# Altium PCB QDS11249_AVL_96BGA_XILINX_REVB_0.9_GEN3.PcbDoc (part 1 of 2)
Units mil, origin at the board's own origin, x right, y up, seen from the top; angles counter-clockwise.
Board outline 3000.03 x 2525.24 mil, 10 copper layers (Top Layer, GND1 - COMMON, INT1, PWR1 - VCC, GND2 - VSS, PWR2 - VCC/VCCIO-EXIT, GND3 - VSSIO, PWR3 - VCCIO, GND4 - COMMON, Bottom Layer), stack 67.702 mil thick; 142 components, 64 nets, 703 pads, 440 vias.
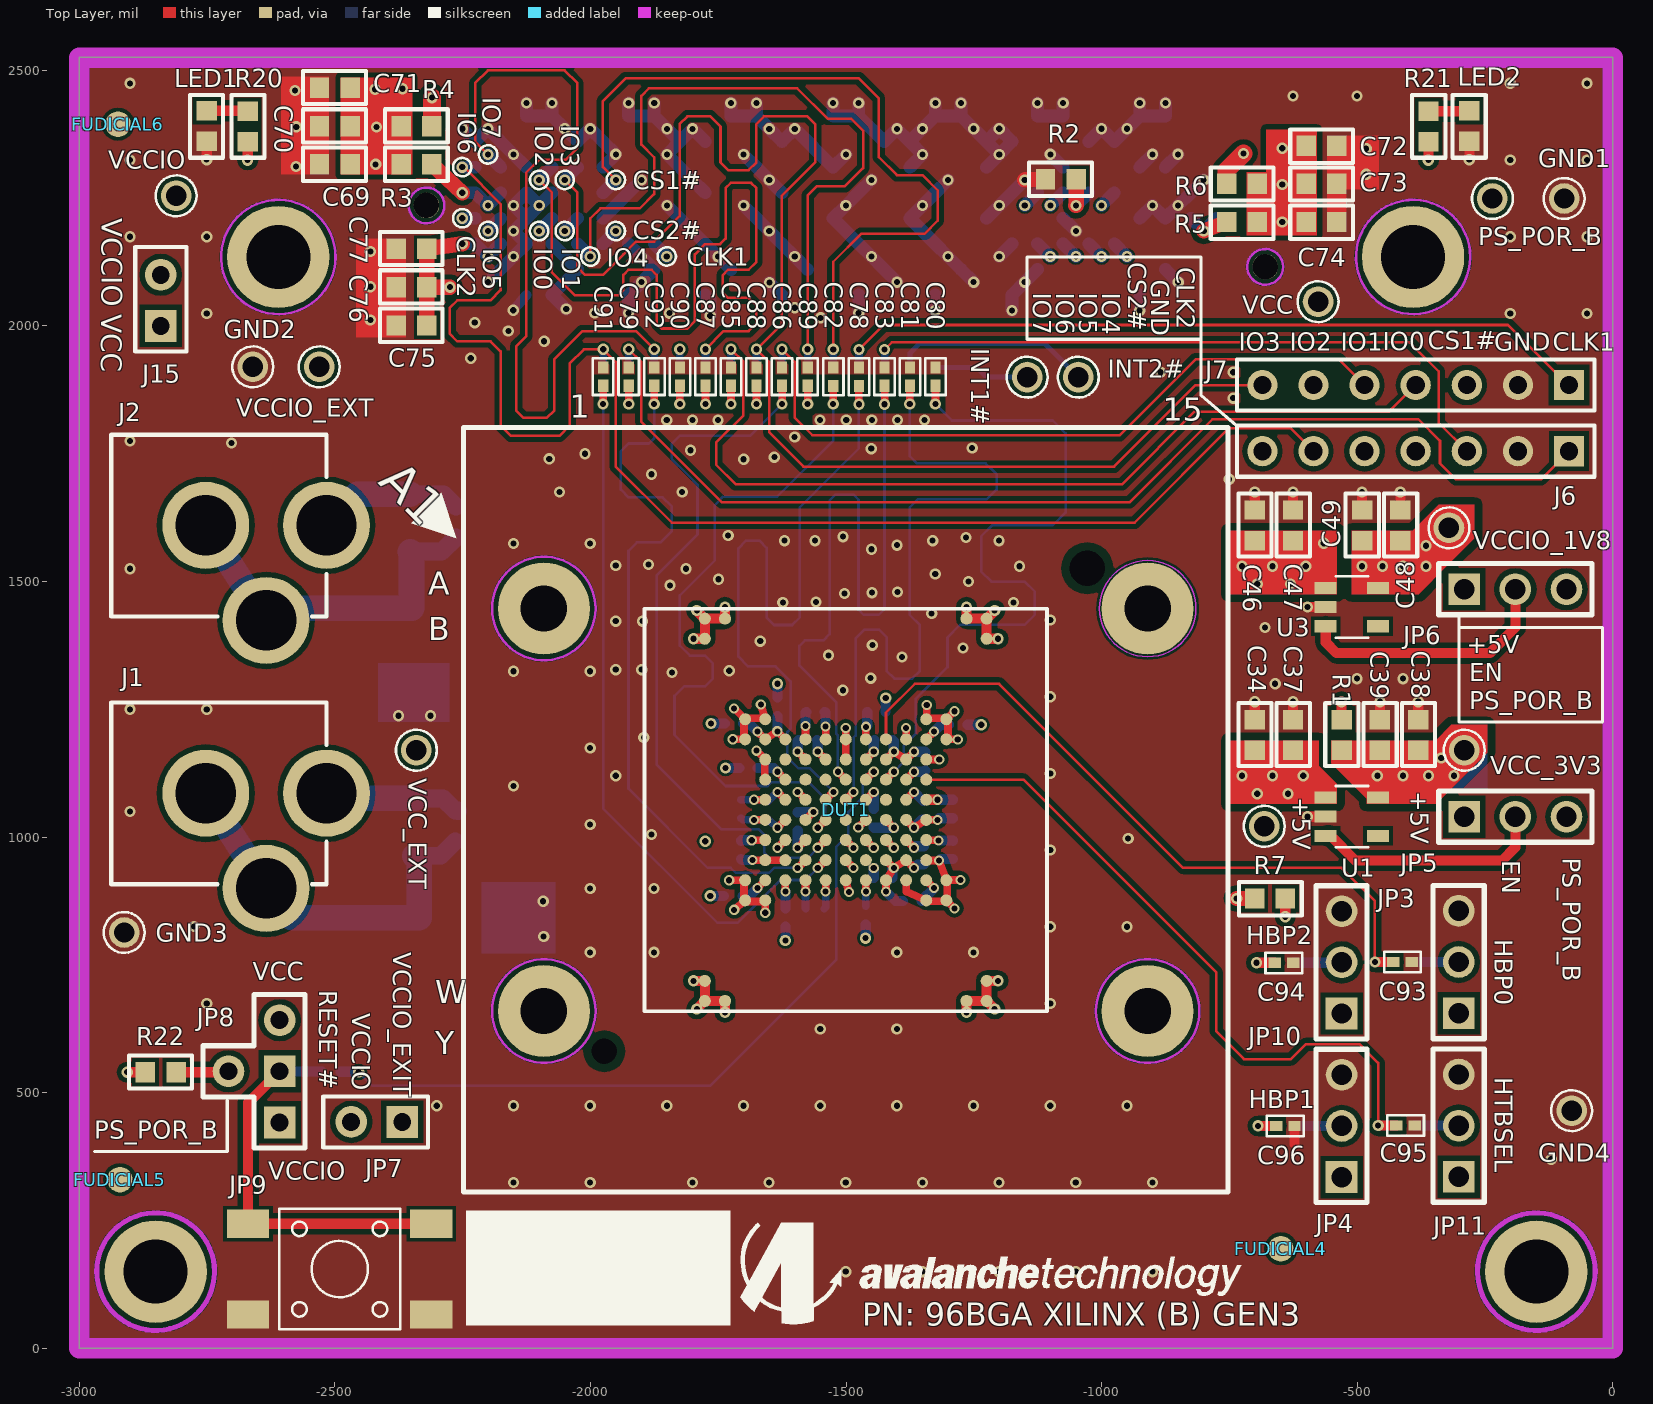
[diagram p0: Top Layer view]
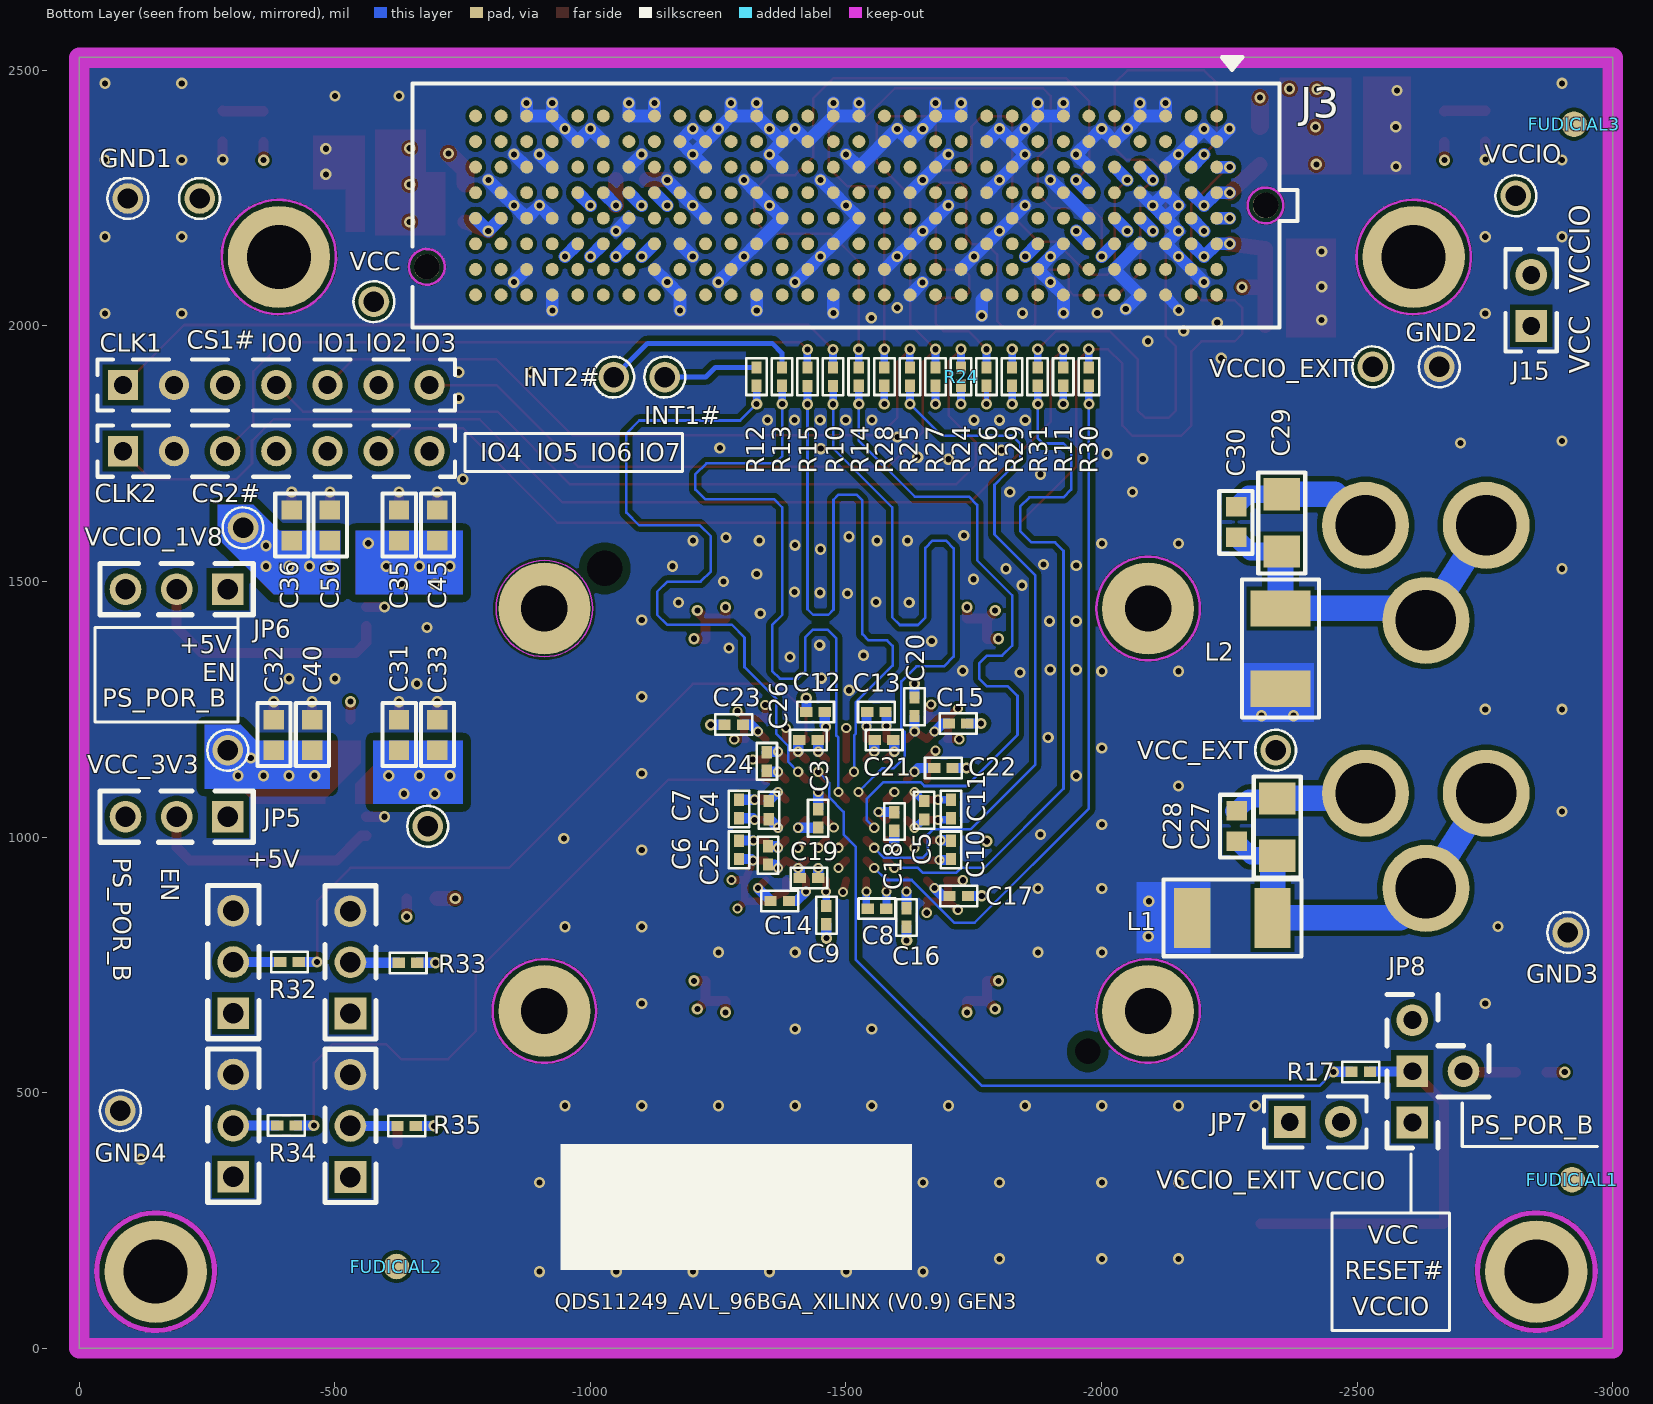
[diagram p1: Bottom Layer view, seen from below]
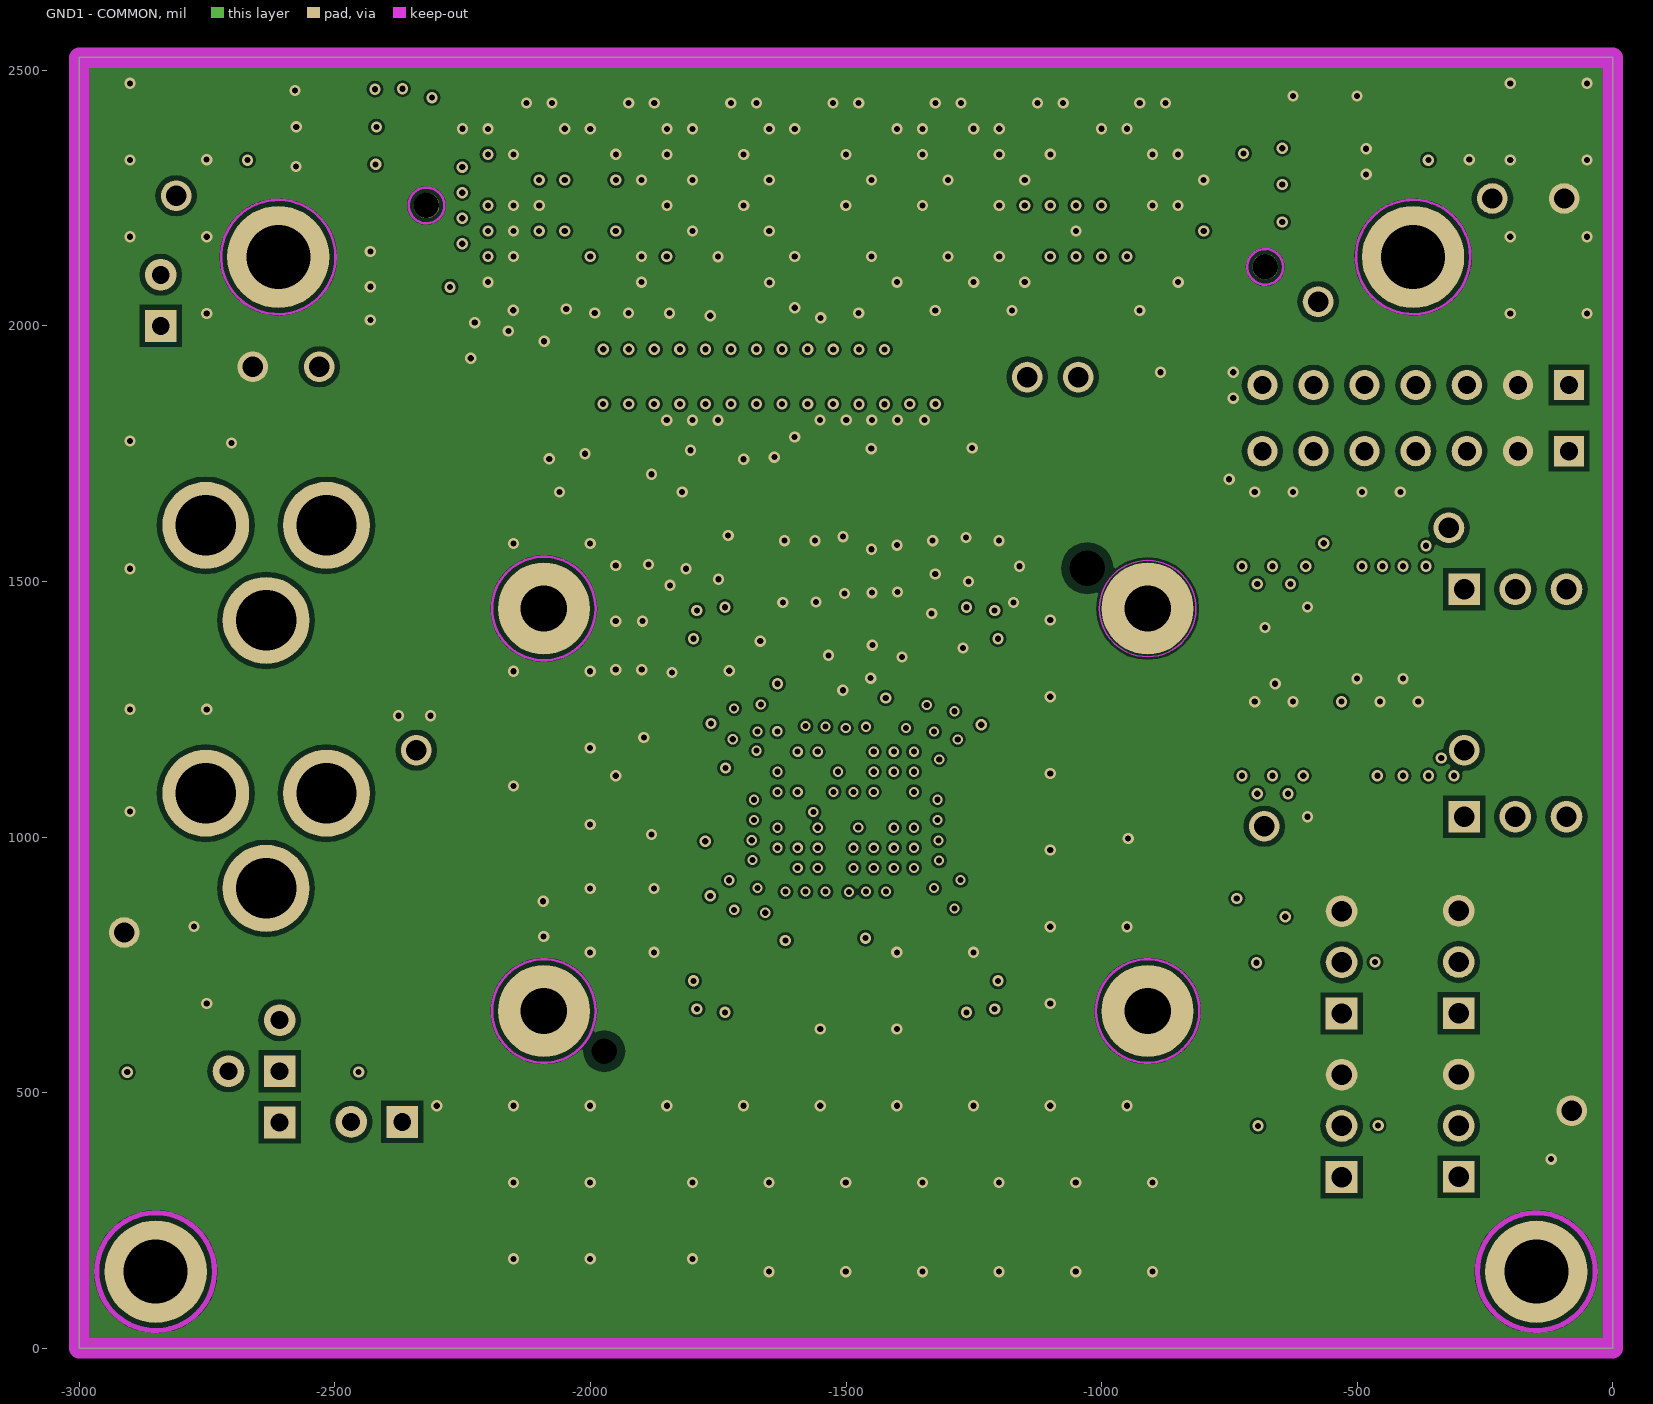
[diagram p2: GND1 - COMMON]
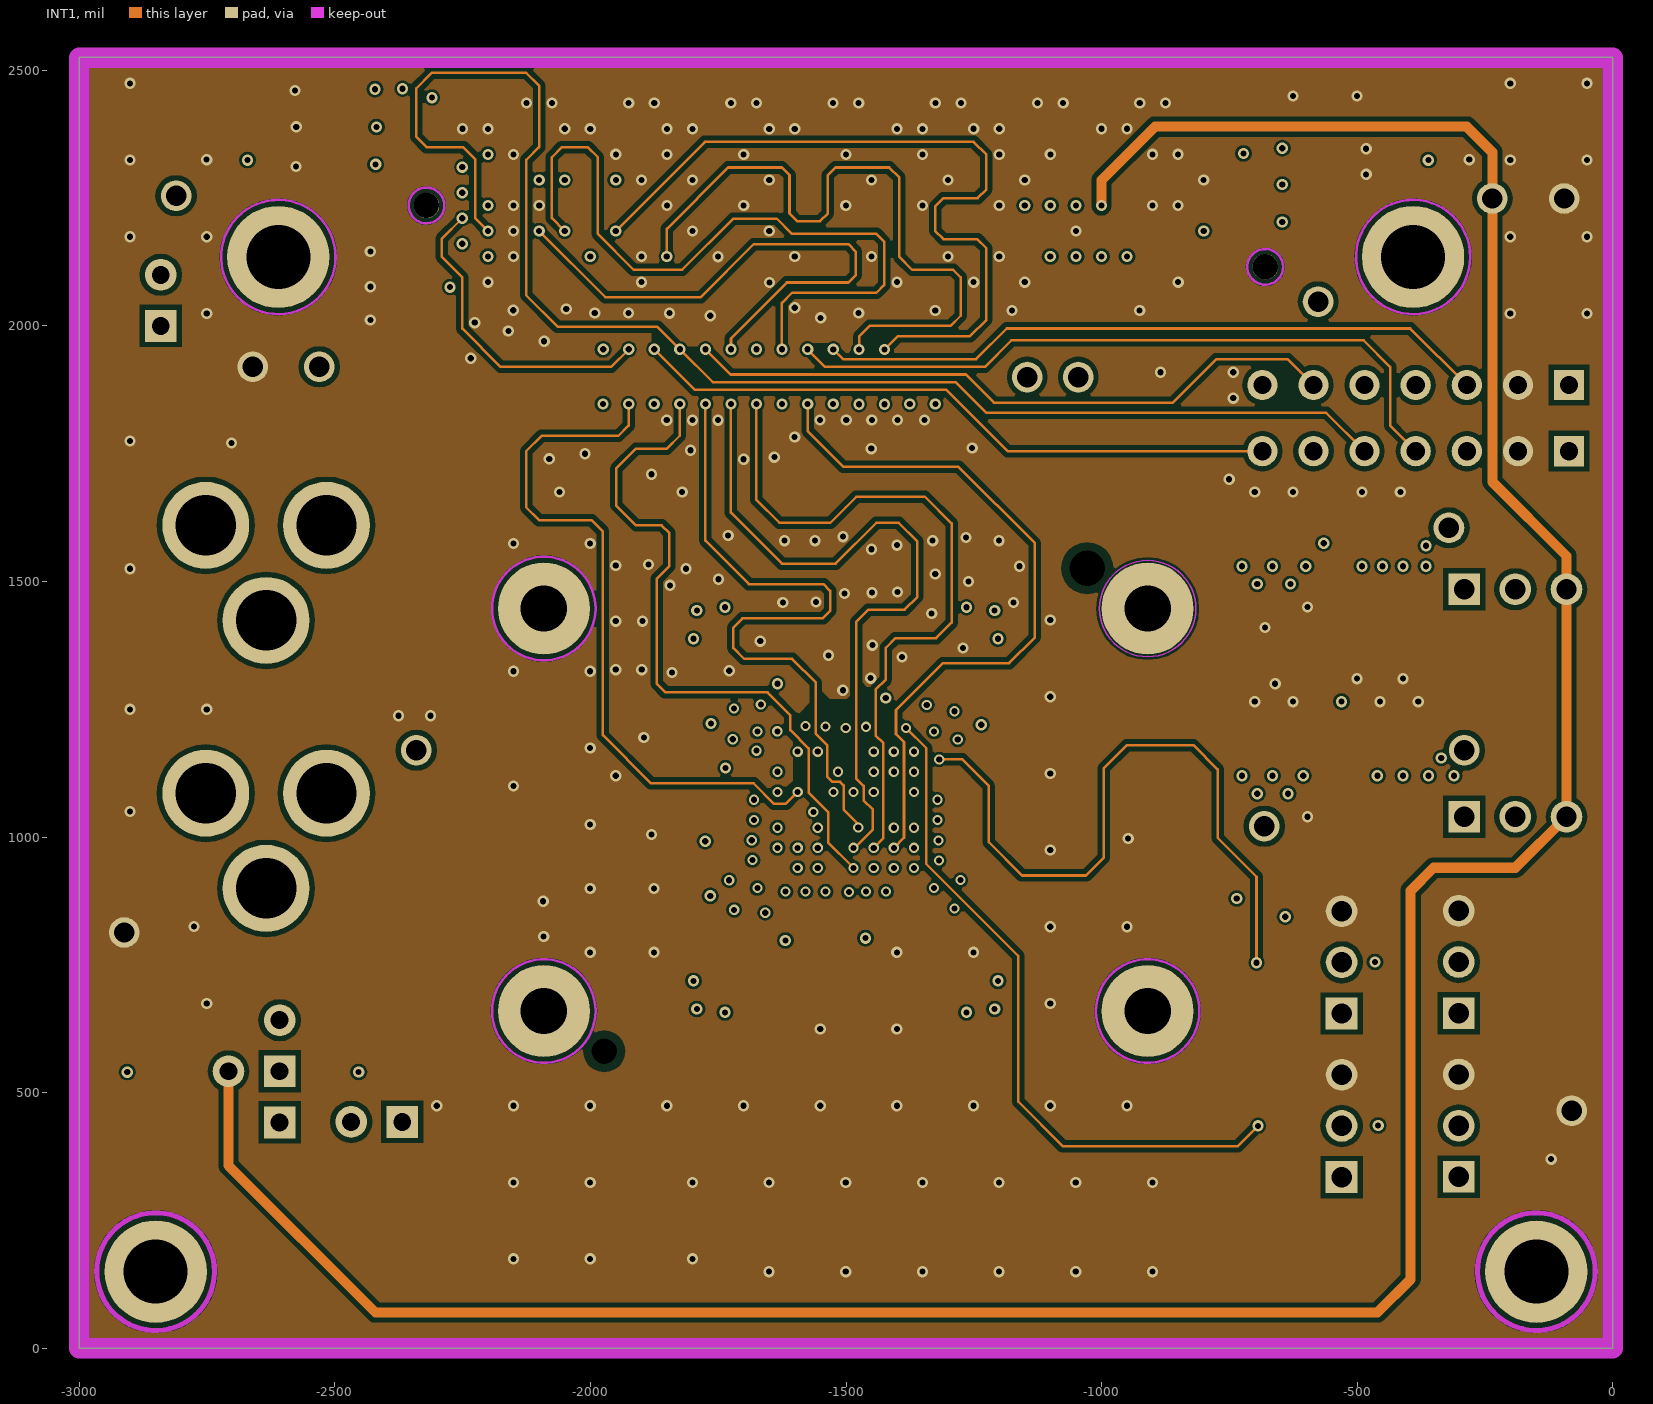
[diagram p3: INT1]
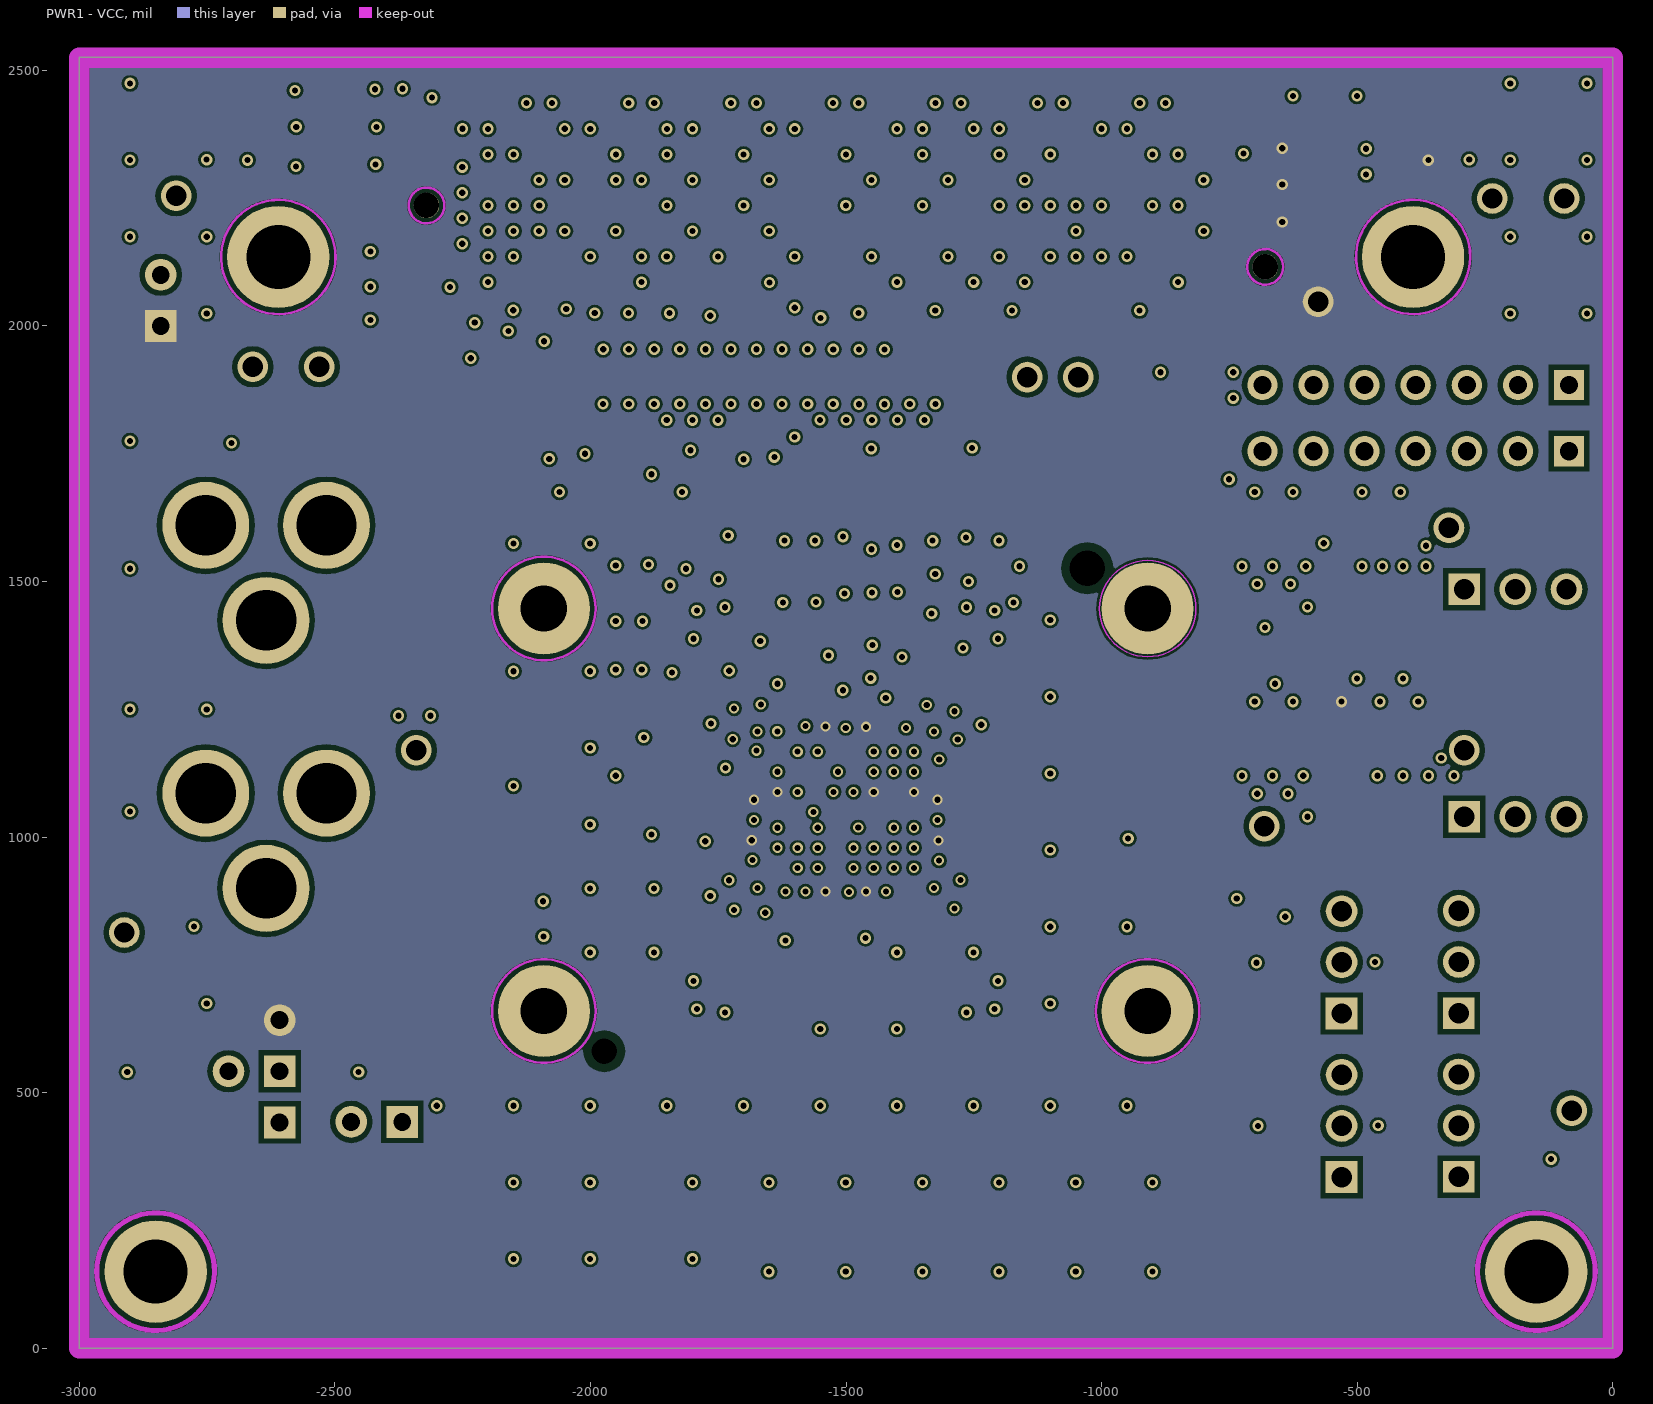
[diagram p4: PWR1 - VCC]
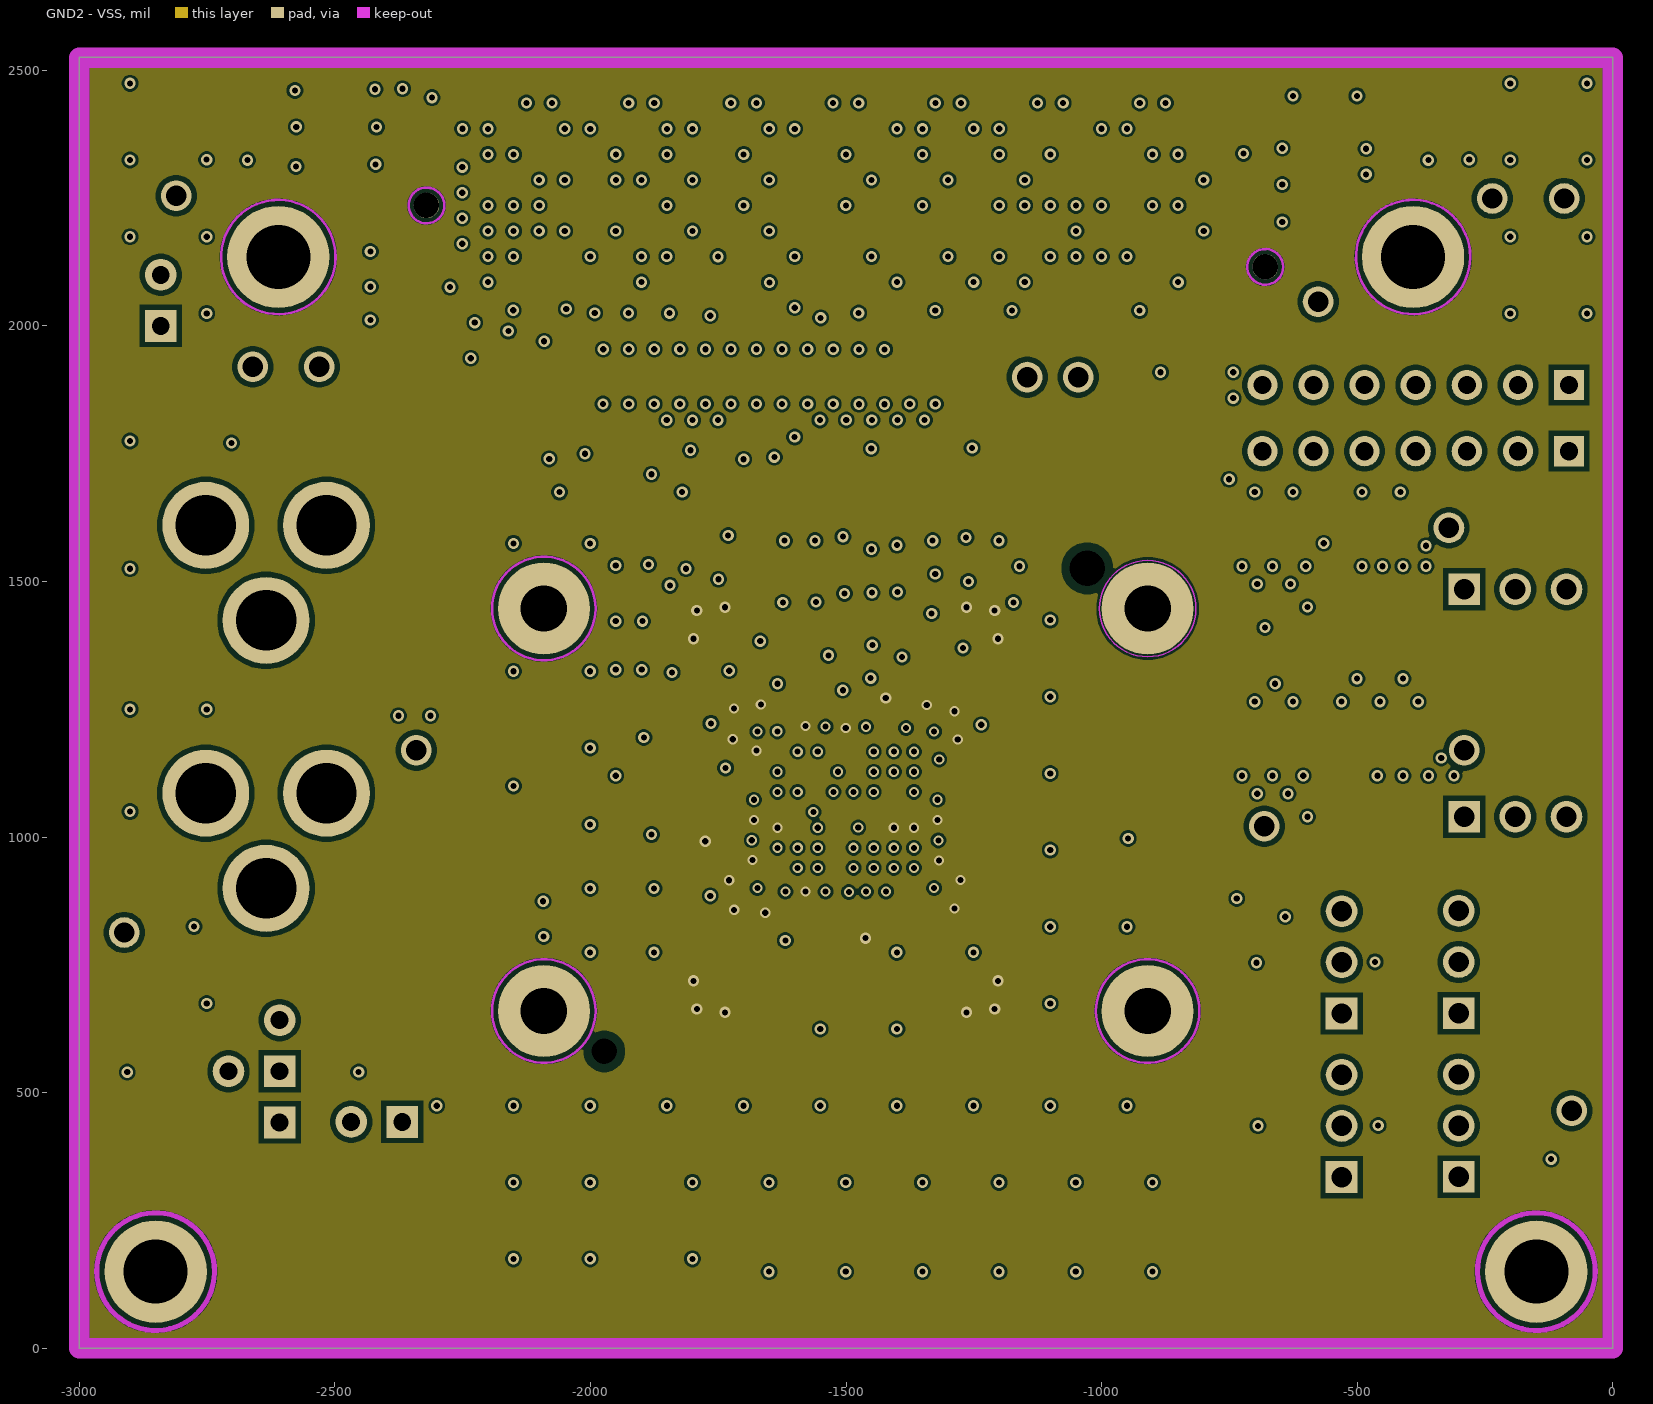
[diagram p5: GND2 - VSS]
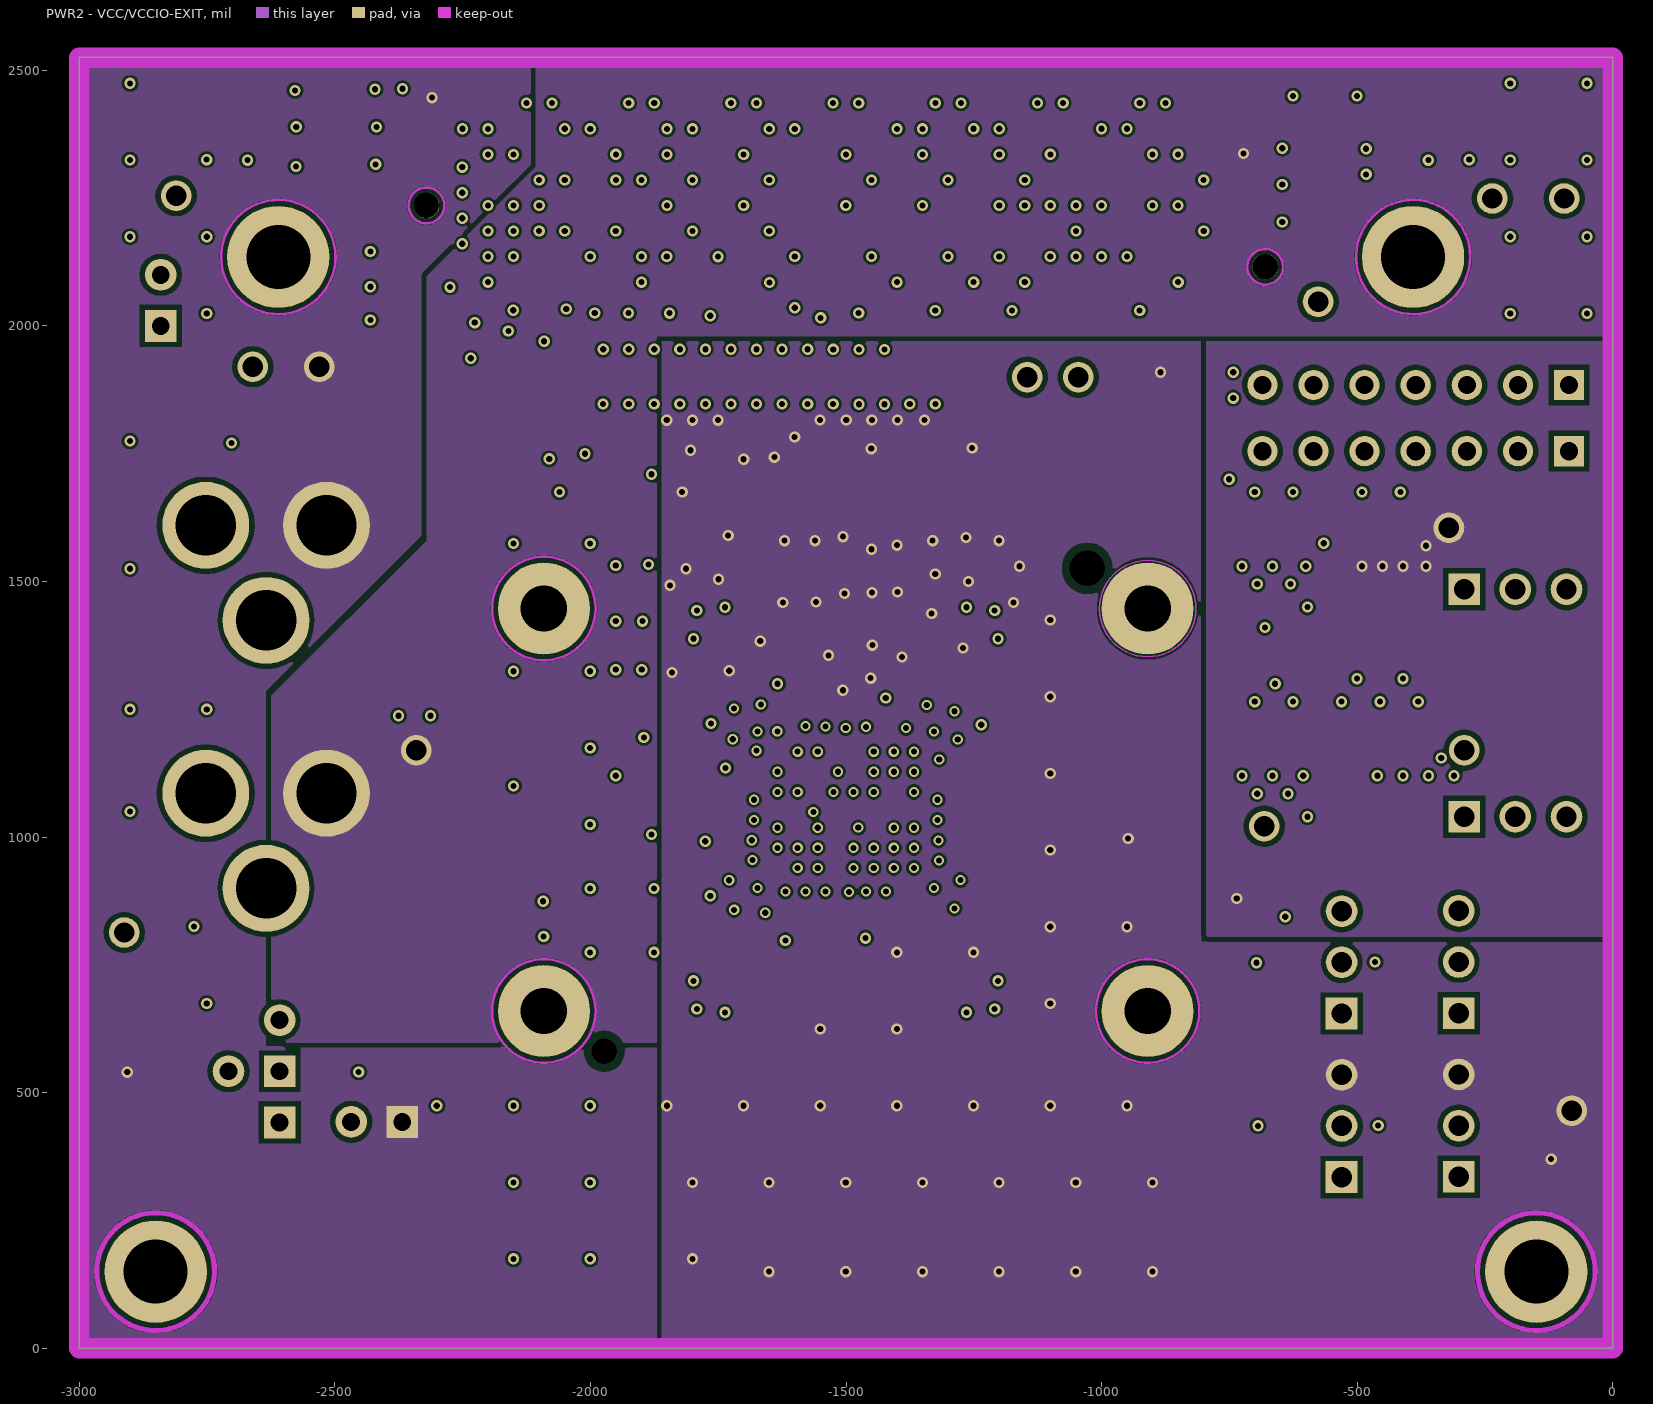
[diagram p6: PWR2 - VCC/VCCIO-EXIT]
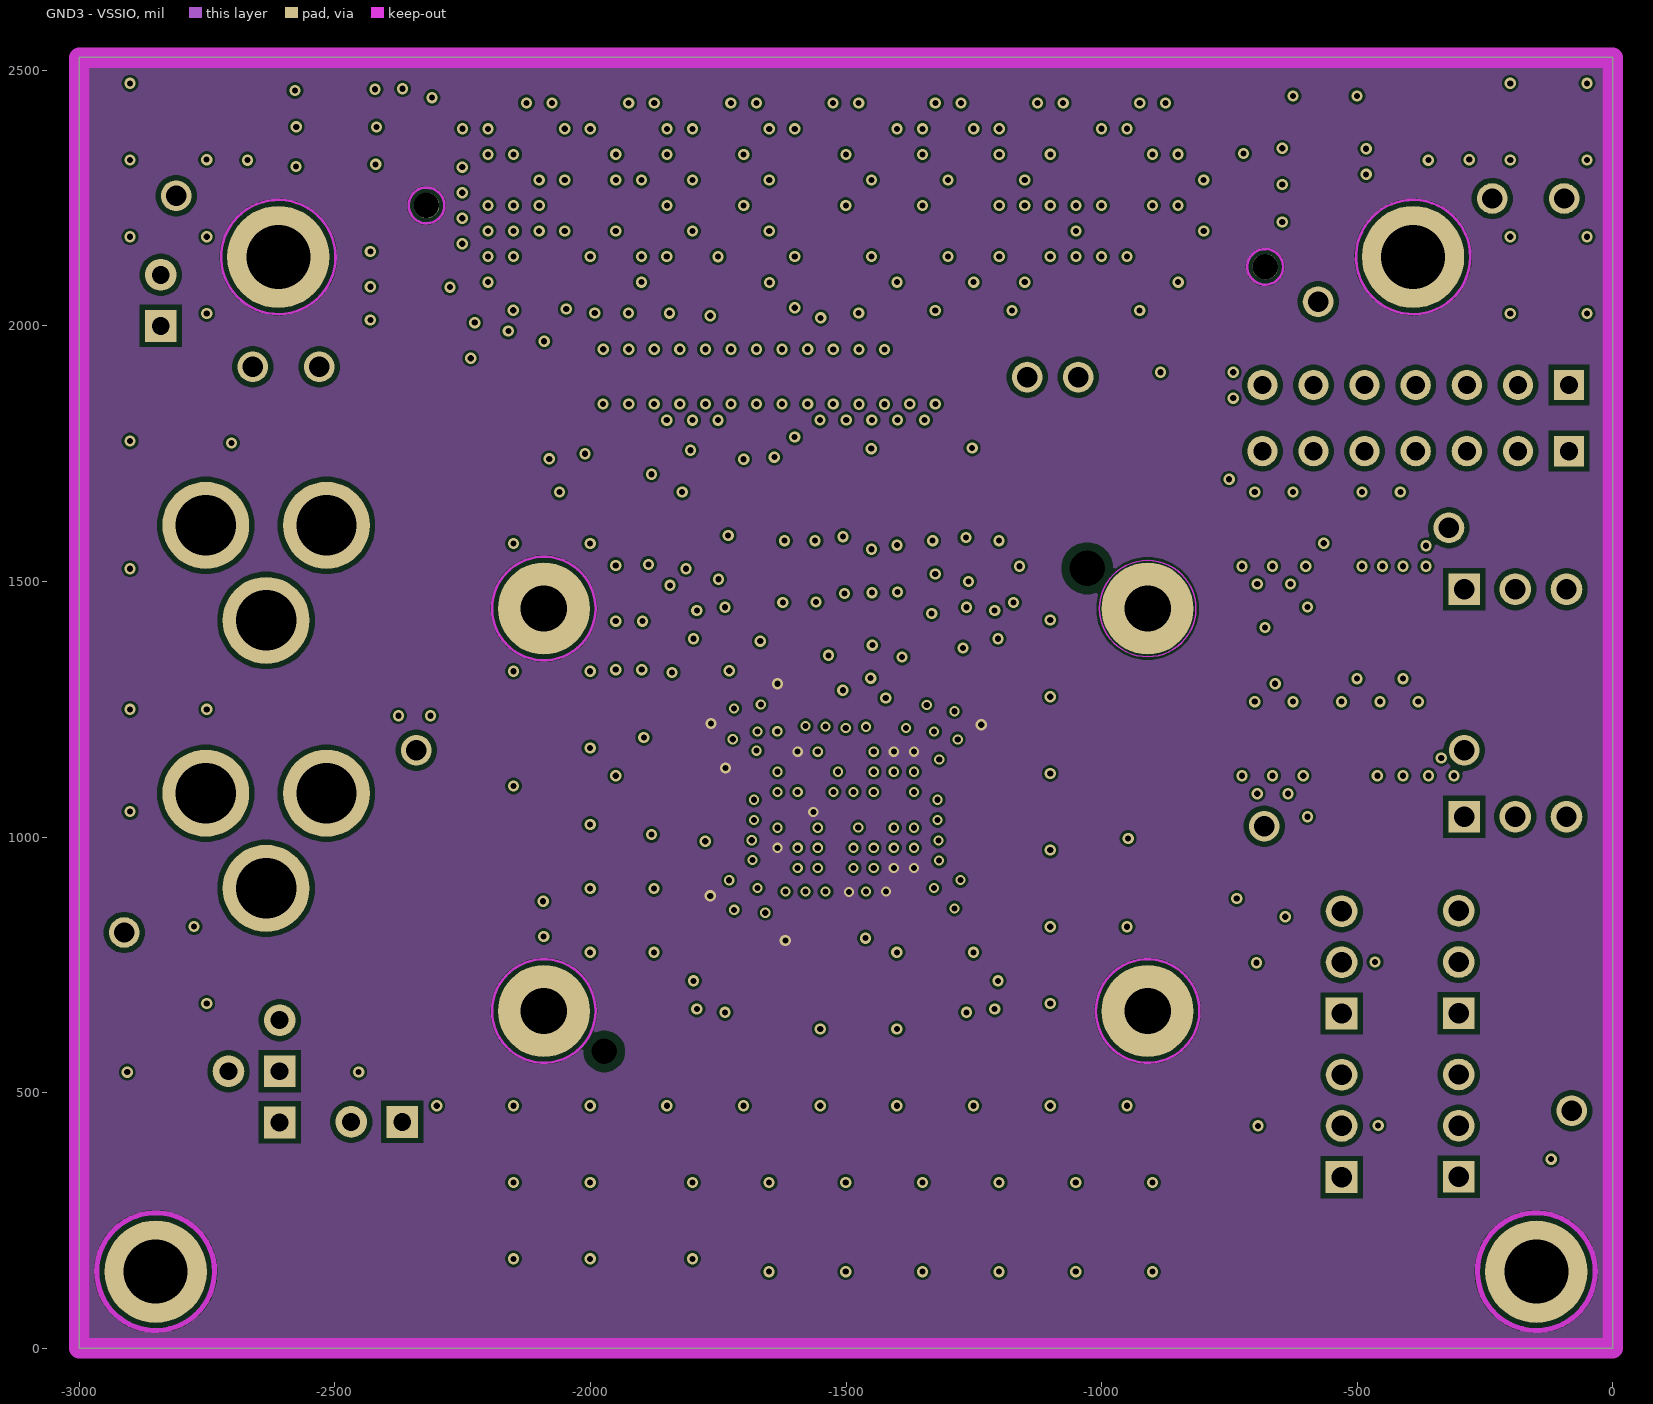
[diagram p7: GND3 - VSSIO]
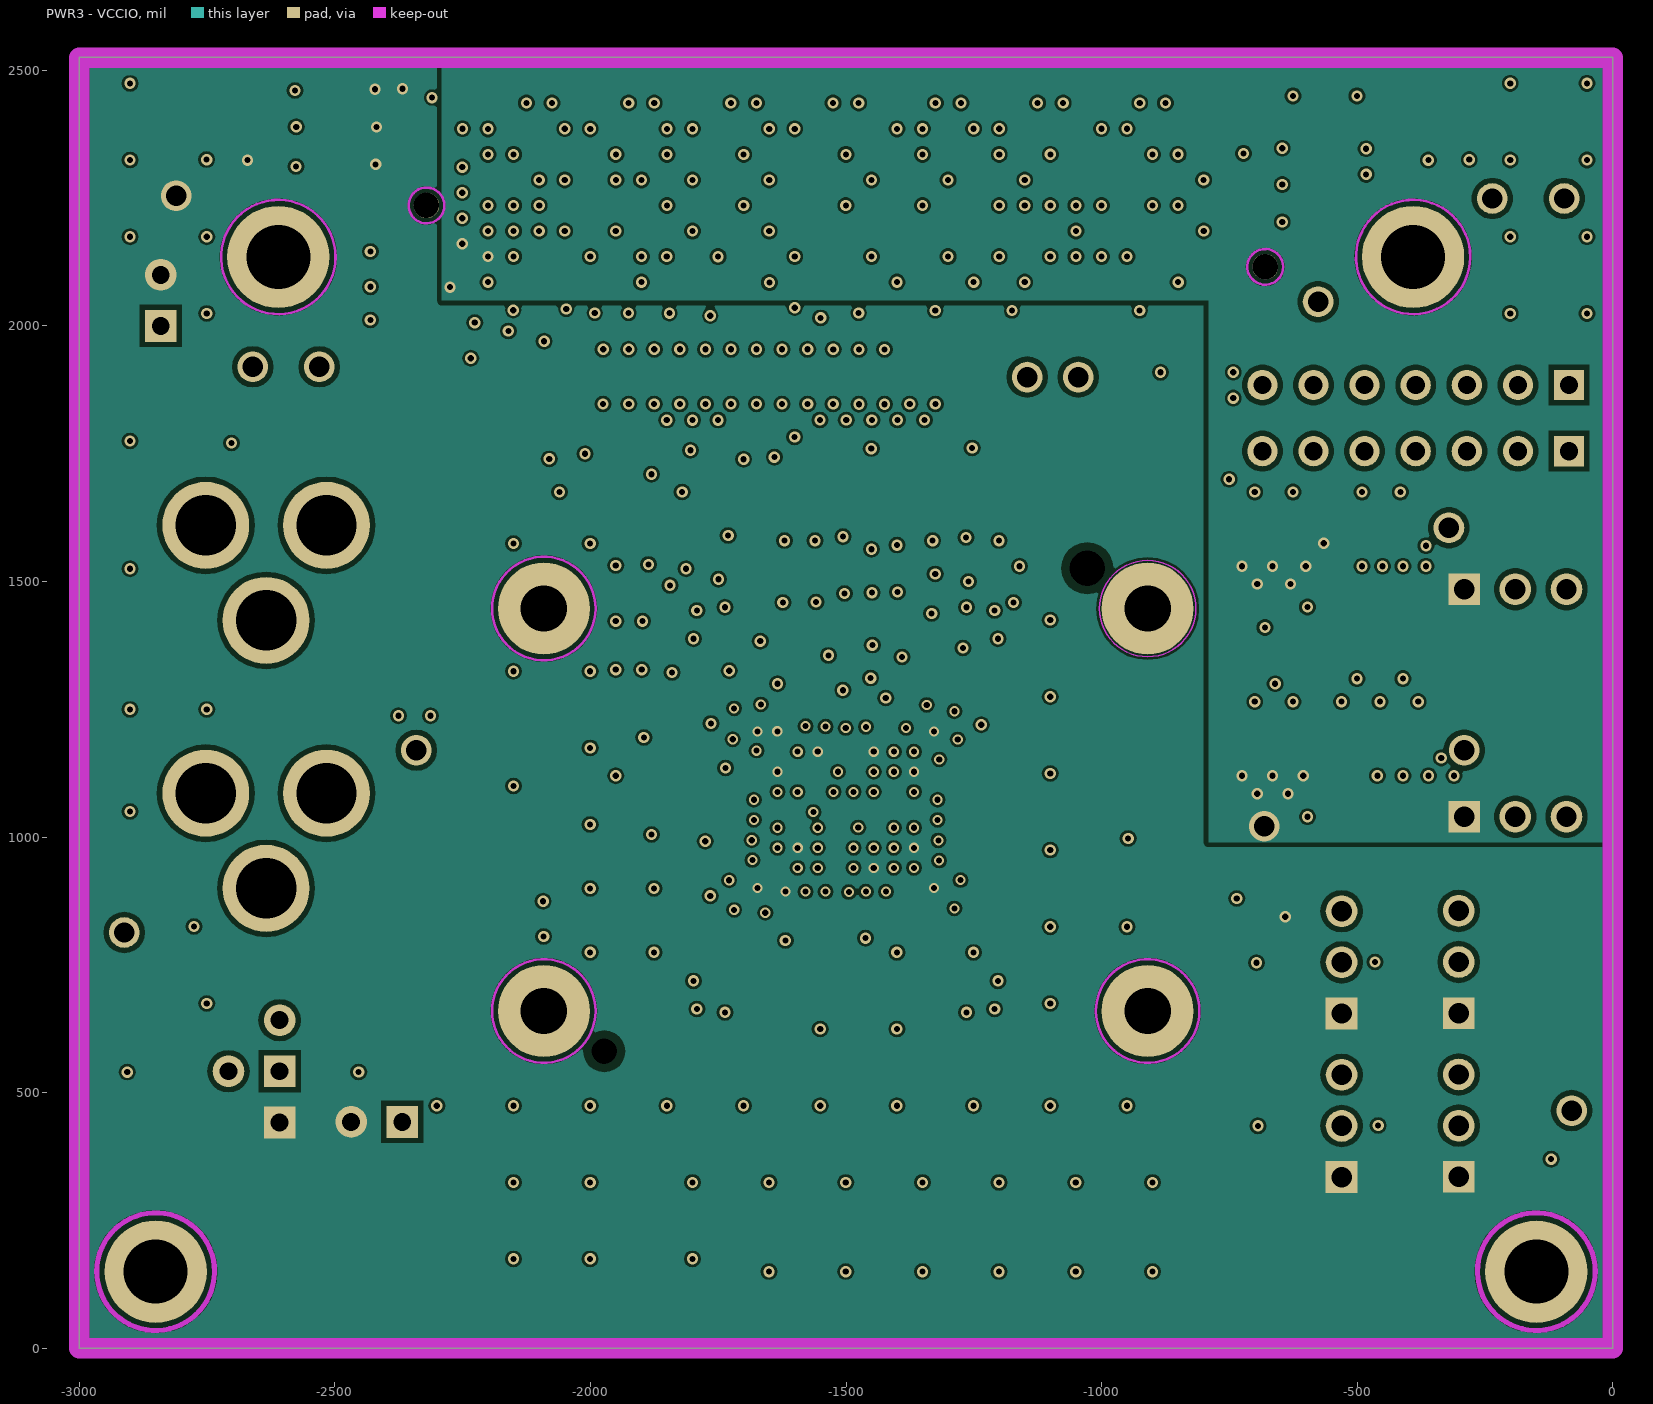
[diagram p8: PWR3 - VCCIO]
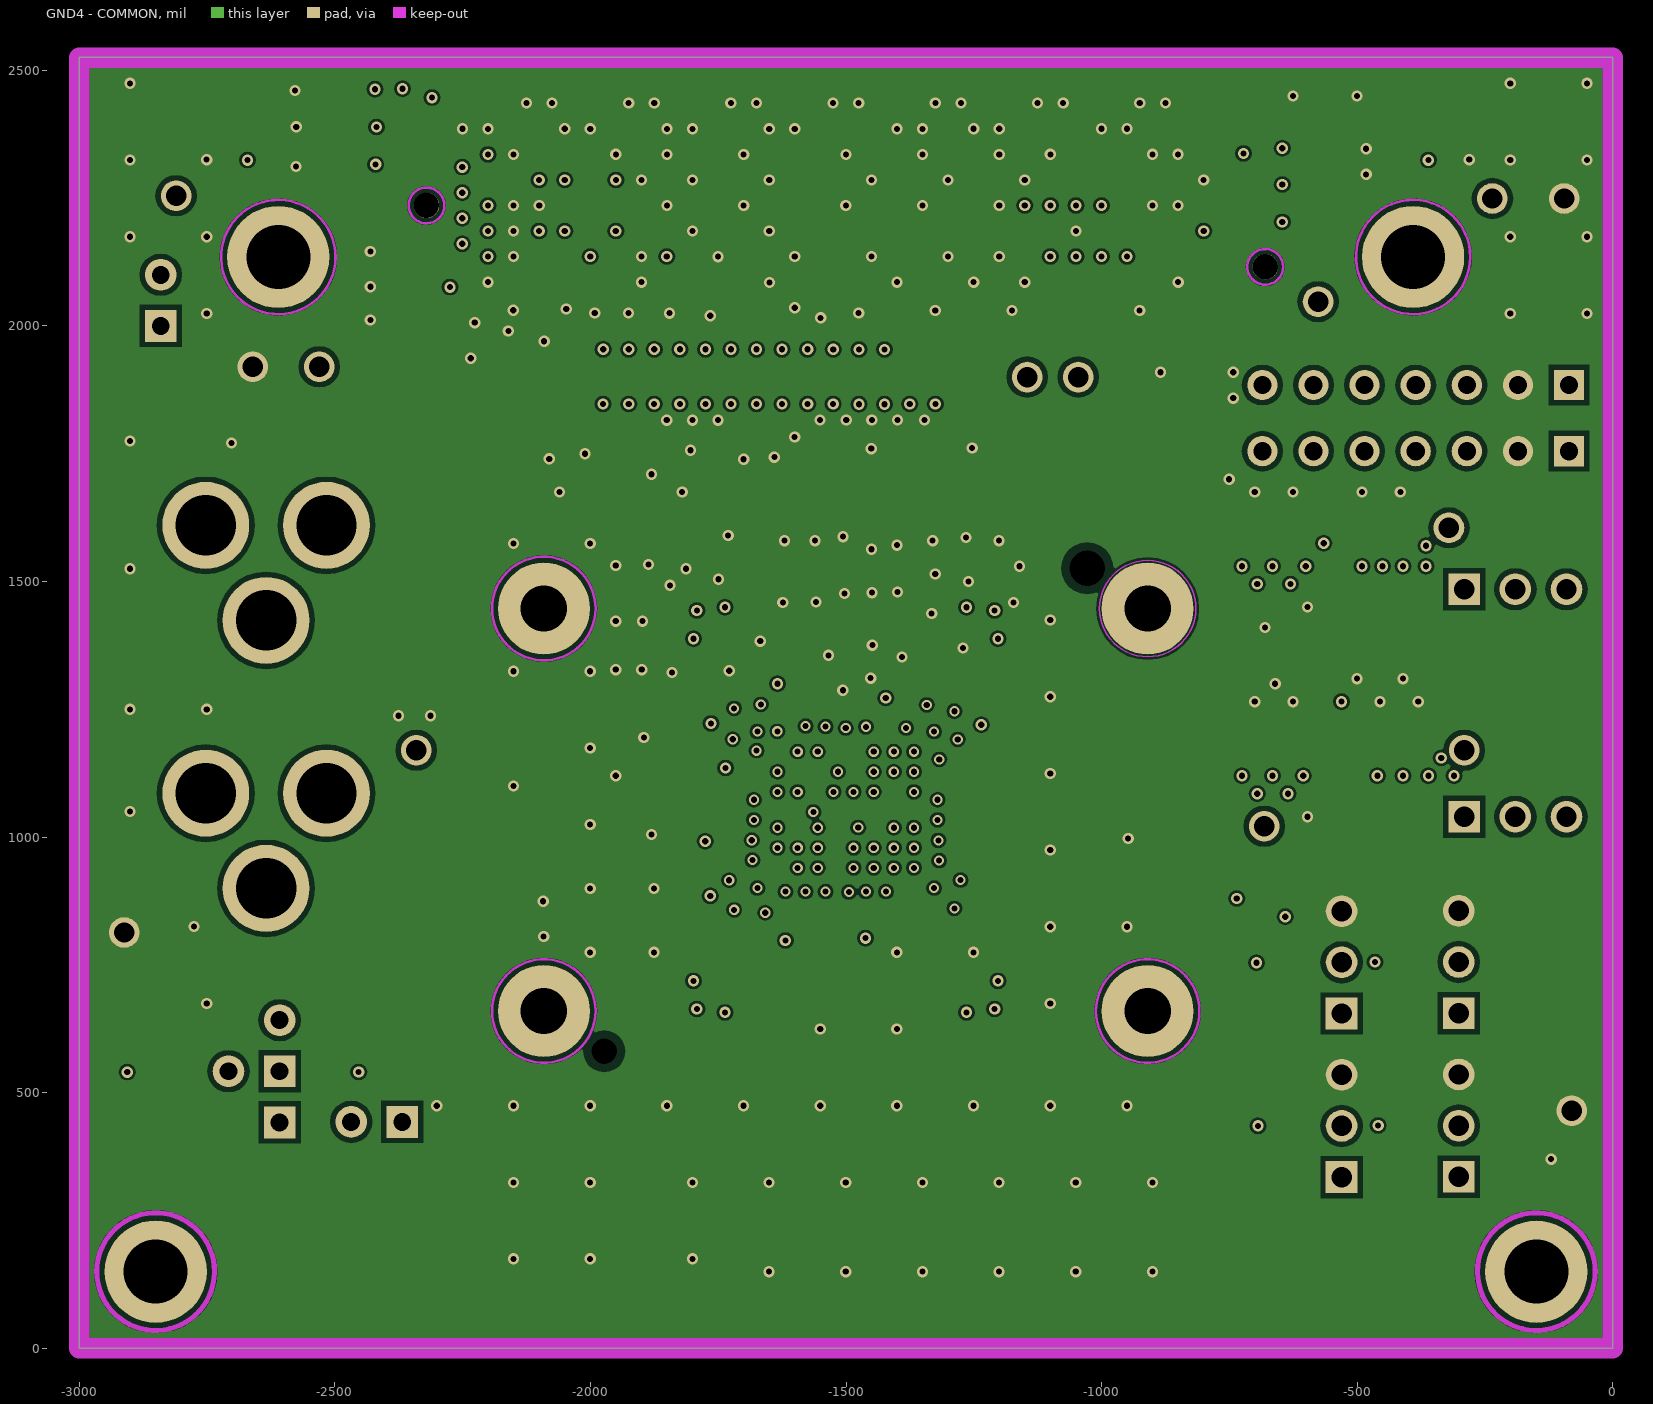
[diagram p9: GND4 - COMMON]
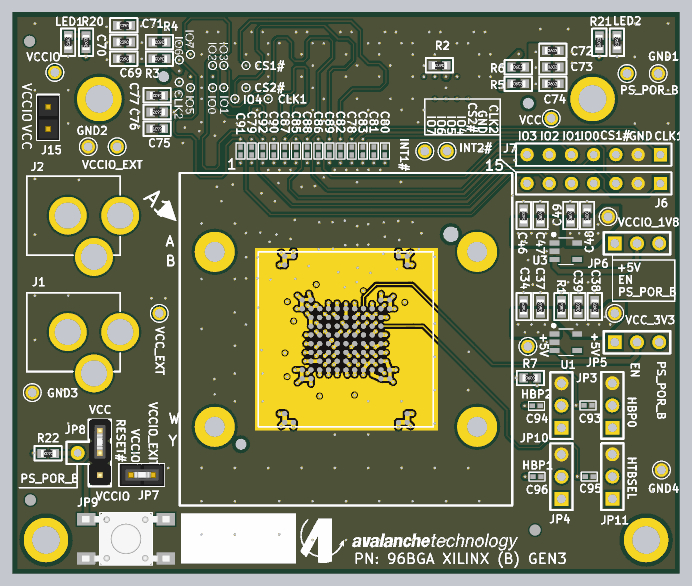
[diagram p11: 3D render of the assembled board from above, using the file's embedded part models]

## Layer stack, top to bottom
Top Solder: solder mask 1, Solder Resist, Dk 3.5
Top Layer: signal copper 6
Dielectric1: core 15, Dk 4.2
GND1 - COMMON: signal copper 1.378
Dielectric 1: prepreg 2.8, Dk 4.1
INT1: signal copper 1.417
Dielectric 2: prepreg 2.8, Dk 4.1
PWR1 - VCC: signal copper 1.417
Dielectric 3: prepreg 2.8, PP-006, Dk 4.1
GND2 - VSS: signal copper 1.378
Dielectric 4: prepreg 2.8, Dk 4.1
PWR2 - VCC/VCCIO-EXIT: signal copper 1.378
Dielectric 8: prepreg 2.8, PP-006, Dk 4.1
GND3 - VSSIO: signal copper 1.378
Dielectric 7: prepreg 2.8, Dk 4.1
PWR3 - VCCIO: signal copper 1.378
Dielectric 5: prepreg 2.8, Dk 4.1
GND4 - COMMON: signal copper 1.378
Dielectric 6: core 10, Dk 4.2
Bottom Layer: signal copper 6
Bottom Solder: solder mask 1, Solder Resist, Dk 3.5

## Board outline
-3000.02,-0.01 -0.02,-0.01 ccw(c-0.02,0) 0,0 0,214.17 0,1725.17 0,2525.22 cw(c-0.02,2525.22) 0,2525.22 ccw(c-0.02,2525.22) -0.02,2525.23 -3000.02,2525.23 ccw(c-3000.02,2525.22) -3000.03,2525.22 -3000.03,1725.22 -3000.03,16.13 -3000.03,0 ccw(c-3000.02,0)

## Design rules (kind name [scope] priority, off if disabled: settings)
Clearance Keepout [All vs OnLayer('Keep-Out Layer')] p1: gap=0 ignorepadtopadclearanceinfootprint=FALSE
Clearance [All] p2: gap=7 ignorepadtopadclearanceinfootprint=FALSE except(5: Arc-Hole Track-SMDPad Track-THPad Track-Via Track-Fill SMDPad-Via THPad-Fill Via-Poly; 10: Arc-Poly Arc-Region Track-Poly SMDPad-SMDPad SMDPad-THPad SMDPad-Region THPad-Poly THPad-Region Via-Region Fill-Poly Poly-Poly; 15: Fill-Region Poly-Region)
ComponentClearance [All] p1 off: gap=10 collisioncheckmode=3 verticalgap=10 showdistances=FALSE
FabricationTestPointUsage TestPointUsage [All] p1: valid=0 allowmultiple=FALSE
FabricationTestpoint Testpoint [(IsPad And (OnTopLayer Or OnBottomLayer))] p1: side=3 testpointundercomponent=TRUE minsize=40 maxsize=100 preferedsize=60 minholesize=0 maxholesize=40 preferedholesize=32 testpointgrid=1 allowsidetop=TRUE allowsidebottom=TRUE usegrid=TRUE gridtolerance=0.01
Height [All] p1 off: minheight=0 maxheight=1000 prefheight=500
HoleSize [All] p1 off: absolutevalues=TRUE maxlimit=100 minlimit=1 maxpercent=80.000 minpercent=20.000
MatchedLengths MG03 [InNetClass('MG03 - Socket to Connector')] p1: tolerance=100 checknetsindiffpair=FALSE checkdiffpairvsdiffpair=TRUE checkxsignals=TRUE checkothers=TRUE
MatchedLengths MG02 [InNetClass('MG02 - R to Connector')] p2: tolerance=100 checknetsindiffpair=FALSE checkdiffpairvsdiffpair=TRUE checkxsignals=TRUE checkothers=TRUE
MatchedLengths MG01 [InNetClass('MG01 - Socket to R')] p3: tolerance=100 checknetsindiffpair=FALSE checkdiffpairvsdiffpair=TRUE checkxsignals=TRUE checkothers=TRUE
PlaneClearance [All] p1: clearance=6
PlaneConnect THERMAL [InComponentClass('THERMAL')] p1: planeconnectstyle=Relief reliefexpansion=20 reliefentries=4 reliefconductorwidth=10 reliefairgap=10
PlaneConnect [All] p2: planeconnectstyle=Direct reliefexpansion=25 reliefentries=4 reliefconductorwidth=10 reliefairgap=12
PolygonConnect THERMAL1 [InComponentClass('Thermal') vs InNet('GND')] p1: connectstyle=Relief reliefconductorwidth=20 reliefentries=4 polygonreliefangle="90 Angle" airgapwidth=20
PolygonConnect [All] p2: connectstyle=Direct reliefconductorwidth=15 reliefentries=4 polygonreliefangle="45 Angle" airgapwidth=15
RoutingVias [All] p1: holewidth=20 width=40 viastyle="Through Hole" minholewidth=20 minwidth=40 maxholewidth=20 maxwidth=40
ShortCircuit [WithinRoom('RoomDefinition_1') & OnTopLayer] p1: allowed=TRUE
SolderMaskExpansion [All] p1: expansion=0 istentingtop=FALSE
Width Width_1 [All] p1: maxlimit=50 minlimit=5 preferedwidth=25
22 further rules are at their usual default settings.

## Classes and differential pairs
net class GROUP2: CLK1_1 CLK2_1 CS1#_1 CS2#_1 INT1#_1 INT2#_1 IO0_1 IO1_1 IO2_1 IO3_1 IO4_1 IO5_1 IO6_1 IO7_1
net class GROUP1: CLK1 CLK2 CS1# CS2# IO0 IO1 IO2 IO3 IO4 IO5 IO6 IO7
component class PAGE03_DC_CONN: C69 C70 C71 C72 C73 C74 C75 C76 C77 J3 R1 R2 R3 R4 R5 R6 R7
component class PAGE02_REGULATOR: +5V C27 C28 C29 C30 C31 C32 C33 C34 C35 C36 C37 C38 C39 C40 C45 C46 C47 C48 C49 C50 C78 C79 C80 C81 C82 C83 C85 C86 C87 C88 C89 C90 C91 C92 C93 C94 C95 C96 CLk2 GND1 GND2 GND3 GND4 INT1# INT2# J1 J2 J6 J7 J15 JP3 JP4 JP5 JP6 JP7 JP8 JP9 JP10 JP11 L1 L2 LED1 LED2 PS_POR_B R10 R11 R12 R13 R14 R15 R17 R20 R21 R22 R24 R25 R26 R27 R28 R29 R30 R31 R32 R33 R34 R35 U1 U3 VCC VCC_3V3 VCC_EXT VCCIO VCCIO_1V8 VCCIO_EXT VDD_1v
component class PAGE01_BGA: C3 C4 C5 C6 C7 C8 C9 C10 C11 C12 C13 C14 C15 C16 C17 C18 C19 C20 C21 C22 C23 C24 C25 C26 DUT1 FUDICIAL1 FUDICIAL2 FUDICIAL3 FUDICIAL4 FUDICIAL5 FUDICIAL6

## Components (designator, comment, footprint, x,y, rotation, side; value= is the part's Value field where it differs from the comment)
+5V "TP" "TEST POINT" -681.73,1021.16 r0 top
C3 "0.1uF" N_0402 -1445.65,1036.76 r270 bottom
C4 "0.01uF" N_0402 -1349.02,1052.71 r270 bottom
C5 "10uF" N_0402 -1653.01,1052.45 r270 bottom
C6 "0.1uF" N_0402 -1290.51,974.95 r270 bottom
C7 "0.1uF" N_0402 -1290.51,1054.95 r270 bottom
C8 "0.1uF" N_0402 -1560.51,859.95 r180 bottom
C9 "0.1uF" N_0402 -1461.58,847.29 r270 bottom
C10 "0.1uF" N_0402 -1705.51,974.95 r270 bottom
C11 "0.1uF" N_0402 -1705.51,1054.95 r270 bottom
C12 "0.1uF" N_0402 -1440.51,1244.95 r0 bottom
C13 "0.1uF" N_0402 -1559.51,1244.95 r180 bottom
C14 "0.1uF" N_0402 -1370.51,874.95 r180 bottom
C15 "0.01uF" N_0402 -1719.29,1222.32 r180 bottom
C16 "10uF" N_0402 -1618.5,842.68 r270 bottom
C17 "0.1uF" N_0402 -1720.51,884.95 r180 bottom
C18 "0.1uF" N_0402 -1594.61,1030.55 r90 bottom
C19 "0.1uF" N_0402 -1427.58,920.14 r0 bottom
C20 "0.1uF" N_0402 -1634.01,1254.95 r90 bottom
C21 "0.1uF" N_0402 -1574.51,1189.95 r180 bottom
C22 "0.1uF" N_0402 -1690.51,1134.95 r180 bottom
C23 "0.1uF" N_0402 -1280.51,1219.95 r0 bottom
C24 "0.1uF" N_0402 -1345.03,1148.06 r90 bottom
C25 "0.1uF" N_0402 -1347.29,964.31 r270 bottom
C26 "0.1uF" N_0402 -1426.51,1189.95 r0 bottom
C27 "DNI" N_1206 -2343.65,1019.57 r270 bottom
C28 "10uF" N_0603 -2264.46,1021.86 r270 bottom
C29 "DNI" N_1206 -2352.5,1614.66 r270 bottom
C30 "10uF" N_0603 -2263.23,1616.35 r270 bottom
C31 "1uF" N_0603 -625.51,1199.95 r90 bottom
C32 "1uF" N_0603 -380.51,1199.95 r90 bottom
C33 "10uF" N_0603 -700.51,1199.95 r90 bottom
C34 "0.1uF" N_0603 -700.51,1199.95 r90 top
C35 "1uF" N_0603 -625.51,1609.95 r90 bottom
C36 "1uF" N_0603 -415.51,1609.95 r90 bottom
C37 "0.01uF" N_0603 -625.51,1199.95 r90 top
C38 "0.01uF" N_0603 -380.51,1199.95 r90 top
C39 "0.1uF" N_0603 -455.51,1199.95 r90 top
C40 "10uF" N_0603 -455.51,1199.95 r90 bottom
C45 "10uF" N_0603 -700.51,1609.95 r90 bottom
C46 "0.1uF" N_0603 -700.51,1609.95 r90 top
C47 "0.01uF" N_0603 -625.51,1609.95 r90 top
C48 "0.01uF" N_0603 -415.51,1609.95 r90 top
C49 "0.1uF" N_0603 -490.51,1609.95 r90 top
C50 "10uF" N_0603 -490.51,1609.95 r90 bottom
C69 "10uF" N_0603 -2500.02,2315.86 r180 top
C70 "0.1uF" N_0603 -2500.02,2390.86 r180 top
C71 "0.01uF" N_0603 -2500.02,2465.86 r180 top
C72 "10uF" N_0603 -570,2352.11 r0 top
C73 "0.1uF" N_0603 -570,2278.29 r0 top
C74 "0.01uF" N_0603 -570,2203.29 r0 top
C75 "10uF" N_0603 -2350.02,2000.86 r180 top
C76 "0.1uF" N_0603 -2350.02,2075.86 r180 top
C77 "0.01uF" N_0603 -2350.02,2150.86 r180 top
C78 "5pf" N_0402 -1474.5,1900.54 r270 top value=5pF
C79 "5pf" N_0402 -1925.02,1900.86 r270 top value=5pF
C80 "5pf" N_0402 -1325.02,1900.86 r270 top value=5pF
C81 "5pf" N_0402 -1375.02,1900.86 r270 top value=5pF
C82 "5pf" N_0402 -1524.93,1900.54 r270 top value=5pF
C83 "5pf" N_0402 -1424.5,1900.86 r270 top value=5pF
C85 "5pf" N_0402 -1725.02,1900.86 r270 top value=5pF
C86 "5pf" N_0402 -1625.02,1900.86 r270 top value=5pF
C87 "5pf" N_0402 -1775.02,1900.86 r270 top value=5pF
C88 "5pf" N_0402 -1675.02,1900.86 r270 top value=5pF
C89 "5pf" N_0402 -1575.02,1900.86 r270 top value=5pF
C90 "5pf" N_0402 -1825.02,1900.86 r270 top value=5pF
C91 "5pf" N_0402 -1975.02,1900.86 r270 top value=5pF
C92 "5pf" N_0402 -1875.02,1900.86 r270 top value=5pF
C93 "5pf" N_0402 -411.33,755.63 r180 top value=5pF
C94 "5pf" N_0402 -643.33,754 r180 top value=5pF
C95 "5pf" N_0402 -405.33,435.63 r180 top value=5pF
C96 "5pf" N_0402 -640.51,434.95 r180 top value=5pF
DUT1 "88-BGA" BGA88 -1500.5,1053.42 r0 top locked
FUDICIAL1 "FUDICIAL" FUDICIAL#1 -2920.51,329.95 r90 top
FUDICIAL2 "FUDICIAL" FUDICIAL#1 -620.51,159.95 r90 top
FUDICIAL3 "FUDICIAL" FUDICIAL#1 -2924.32,2394.71 r90 top
FUDICIAL4 "FUDICIAL" FUDICIAL#2 -649.32,194.71 r90 top
FUDICIAL5 "FUDICIAL" FUDICIAL#2 -2920.51,329.95 r90 top
FUDICIAL6 "FUDICIAL" FUDICIAL#2 -2924.32,2394.71 r90 top
GND1 "TP" "TEST POINT" -95.17,2249.3 r90 top
GND2 "TP" "TEST POINT" -2660.51,1919.95 r90 top
GND3 "TP" "TEST POINT" -2912.05,813.42 r90 top
GND4 "TP" "TEST POINT" -80.51,464.95 r90 top
INT1# "TP" "TEST POINT" -1145.51,1899.95 r90 top
INT2# "TP" "TEST POINT" -1045.51,1899.95 r90 top
J1 "POWER_JACK" POWER_JACK_PTH -3056.46,1085.86 r270 top
J2 "POWER_JACK" POWER_JACK_PTH -3056.46,1609.95 r270 top
J3 "SEAM-30-02.0-L-08-1-A-K-TR" SAMTEC_SEAM-30-02.0-L-08-1-A-K-TR -1500.29,2235.66 r180 bottom locked
J6 "HDR-8" HDR1X7 -85.51,1754.95 r180 top
J7 "HDR-8" HDR1X7 -85.51,1884.22 r180 top
J15 "HDR-2PIN" HDR-2 -2840.51,1999.95 r90 top
JP3 "3PIN_JUMPER" JUMPER_3PIN -301.33,755.63 r90 top
JP4 "3PIN_JUMPER" JUMPER_3PIN -530.51,434.95 r90 top
JP5 "3PIN_JUMPER" JUMPER_3PIN -190.51,1039.95 r0 top
JP6 "3PIN_JUMPER" JUMPER_3PIN -190.51,1484.95 r0 top
JP7 "HDR-TH_2P-P2.54" "1X2 HEADER WITH SHUNT_051914" -2368.02,442.86 r180 top
JP8 "4PIN_JUMPER" JUMPER_4PIN -2608.02,441.86 r90 top
JP9 "SW-SMD_4P_6X6" SW-SMD_4P_6X6 -2490.51,154.95 r0 top
JP10 "3PIN_JUMPER" JUMPER_3PIN -530.51,754.95 r90 top
JP11 "3PIN_JUMPER" JUMPER_3PIN -301.33,435.63 r90 top
L1 "2743019447" FB_2743019447 -2255.96,841.86 r180 bottom
L2 "2743019447" FB_2743019447 -2350.02,1368.89 r90 bottom
LED1 "RED" N_0603 -2750.51,2390.95 r270 top
LED2 "RED" N_0603 -280.51,2390.95 r270 top
PS_POR_B "TP" "TEST POINT" -235.51,2249.3 r90 top
R1 "DNI" N_0603 -530.51,1199.95 r90 top
R2 "0" N_0603 -1079.69,2286.58 r180 top
R3 "0" N_0603 -2340.02,2315.86 r180 top
R4 "DNI" N_0603 -2340.02,2390.86 r180 top
R5 "0" N_0603 -725.49,2203.29 r0 top
R6 "DNI" N_0603 -725.49,2278.29 r0 top
R7 "DNI" N_0603 -670.51,879.95 r0 top
R10 "39 1%" N_0402 -1474.5,1900.54 r270 bottom
R11 "39 1%" N_0402 -1925.02,1900.86 r270 bottom
R12 "39 1%" N_0402 -1325.02,1900.86 r270 bottom
R13 "39 1%" N_0402 -1375.02,1900.86 r270 bottom
R14 "39 1%" N_0402 -1524.93,1900.85 r270 bottom
R15 "39 1%" N_0402 -1424.5,1900.54 r270 bottom
R17 "39 1%" N_0402 -2507.02,540.86 r0 bottom
R20 "666" N_0603 -2670.51,2389.95 r90 top
R21 "261" N_0603 -360.51,2389.95 r90 top
R22 "4.7K" N_0603 -2840.51,539.95 r180 top
R24 "39 1%" N_0402 -1725.02,1900.86 r270 bottom
R25 "39 1%" N_0402 -1625.02,1900.86 r270 bottom
R26 "39 1%" N_0402 -1775.02,1900.86 r270 bottom
R27 "39 1%" N_0402 -1675.02,1900.86 r270 bottom
R28 "39 1%" N_0402 -1575.02,1900.86 r270 bottom
R29 "39 1%" N_0402 -1825.02,1900.86 r270 bottom
R30 "39 1%" N_0402 -1975.02,1900.86 r270 bottom
R31 "39 1%" N_0402 -1875.02,1900.86 r270 bottom
R32 "39 1%" N_0402 -411.33,755.63 r180 bottom
R33 "39 1%" N_0402 -643.33,754 r180 bottom
R34 "39 1%" N_0402 -405.33,435.63 r180 bottom
R35 "39 1%" N_0402 -640.51,434.95 r180 bottom
U1 "TLV75733PDBVR" SOT23-5 -510.51,1039.95 r0 top
U3 "TLV75718PDBVR" SOT23-5 -510.51,1449.95 r0 top
VCC "TP" "TEST POINT" -576.5,2047.54 r0 top
VCC_3V3 "TP" "TEST POINT" -290.51,1169.95 r90 top
VCC_EXT "TESTPOINT" "TEST POINT" -2340.51,1169.95 r0 top
VCCIO "TP" "TEST POINT" -2810.5,2254.54 r90 top
VCCIO_1V8 "TP" "TEST POINT" -320.51,1604.95 r90 top
VCCIO_EXT "TESTPOINT" "TEST POINT" -2530.51,1919.95 r90 top

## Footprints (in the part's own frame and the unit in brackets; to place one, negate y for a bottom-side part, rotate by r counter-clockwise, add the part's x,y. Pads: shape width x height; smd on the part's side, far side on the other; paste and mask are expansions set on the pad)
"1X2 HEADER WITH SHUNT_051914" [mil] "TH"
  rect 62x62 hole 35: 1(0,0)
  round 62 hole 35: 2(100,0)
  silkscreen extent -50,-50 155,50, body extent -50,-50 150,50, height 332
BGA88 [mm]
  round 0.6 smd: A1(-7,9.5) A2(-6,9.5) A14(6,9.5) A15(7,9.5) B1(-7,8.5) B15(7,8.5) F3(-5,4.5) F4(-4,4.5) F12(4,4.5) F13(5,4.5) G3(-5,3.5) G4(-4,3.5) G5(-3,3.5) G6(-2,3.5) G7(-1,3.5) G8(0,3.5) G9(1,3.5) G10(2,3.5) G11(3,3.5) G12(4,3.5) G13(5,3.5) H4(-4,2.5) H5(-3,2.5) H6(-2,2.5) H7(-1,2.5) H8(0,2.5) H9(1,2.5) H10(2,2.5) H11(3,2.5) H12(4,2.5) J4(-4,1.5) J5(-3,1.5) J6(-2,1.5) J7(-1,1.5) J8(0,1.5) J9(1,1.5) J10(2,1.5) J11(3,1.5) J12(4,1.5) K4(-4,0.5) K5(-3,0.5) K6(-2,0.5) K7(-1,0.5) K8(0,0.5) K9(1,0.5) K10(2,0.5) K11(3,0.5) K12(4,0.5) L4(-4,-0.5) L5(-3,-0.5) L6(-2,-0.5) L7(-1,-0.5) L8(0,-0.5) L9(1,-0.5) L10(2,-0.5) L11(3,-0.5) L12(4,-0.5) M4(-4,-1.5) M5(-3,-1.5) M6(-2,-1.5) M7(-1,-1.5) M8(0,-1.5) M9(1,-1.5) M10(2,-1.5) M11(3,-1.5) M12(4,-1.5) N4(-4,-2.5) N5(-3,-2.5) N6(-2,-2.5) N7(-1,-2.5) N8(0,-2.5) N9(1,-2.5) N10(2,-2.5) N11(3,-2.5) N12(4,-2.5) P3(-5,-3.5) P4(-4,-3.5) P5(-3,-3.5) P6(-2,-3.5) P7(-1,-3.5) P8(0,-3.5) P9(1,-3.5) P10(2,-3.5) P11(3,-3.5) P12(4,-3.5) P13(5,-3.5) R3(-5,-4.5) R4(-4,-4.5) R12(4,-4.5) R13(5,-4.5) W1(-7,-8.5) W15(7,-8.5) Y1(-7,-9.5) Y2(-6,-9.5) Y14(6,-9.5) Y15(7,-9.5)
  round 0.762 hole 1.27 unplated: GUIDEPIN_1.55_NP(-12,-12)
  round 0.762 hole 1.778 unplated: GUIDEPIN_2.05_NP(12,12)
  round 4.572 hole 2.3: HOLE2.3(-15,-10) HOLE2.3(-15,10) HOLE2.3(15,-10) HOLE2.3(15,10)
  round 0.381 on Mech2: ORIGIN(0,0)
  silkscreen extent -21.6,-19 19,19
FB_2743019447 [mil]
  rect 71x118 smd mask+2: 1(-78.5,0) 2(78.5,0)
  silkscreen extent -135,-75 135,75
FUDICIAL#1 [mil]
  round 50 smd far side: FUDICIAL(0,0)
FUDICIAL#2 [mil]
  round 50 smd: FUDICIAL(0,0)
HDR1X7 [mm] "Connector; Header; 8 Position"
  rect 1.5x1.5 hole 0.9: 1(0,0)
  round 1.5 hole 0.9: 2(2.54,0) 3(5.08,0) 4(7.62,0) 5(10.16,0) 6(12.7,0) 7(15.24,0)
  silkscreen extent -1.27,-1.27 16.51,1.27
HDR-2 [mil] "TH"
  rect 62x62 hole 35: 1(0,0)
  round 62 hole 35: 2(100,0)
  silkscreen extent -50,-50 155,50, body extent -50,-50 150,50, height 332
JUMPER_3PIN [mil]
  rect 62x62 hole 40: 1(-100,0)
  round 62 hole 40: 2(0,0) 3(100,0)
  silkscreen extent -150,-50 150,50
JUMPER_4PIN [mil] "TH"
  rect 62x62 hole 35: 1(100,0) 2(0,0)
  round 62 hole 35: 3(200,0) 4(100,100)
  silkscreen extent -50,-50 250,150, body extent -46,-49 254,49, height 323
N_0402 [mil] "Chip Capacitor, Body 1.0x0.5mm, IPC High Density"
  rect 24x20 smd: 1(-18,0) 2(18,0)
  round 20 on Mech2: ""(0,0)
  silkscreen extent -36,-20 36,20, body extent -22,-12 22,12, height 51
N_0603 [mil]
  rect 38x40 smd: 1(-30,0) 2(30,0)
  silkscreen extent -61,-33 62,32, body extent -34,-16 32,16, height 22
N_1206 [mm]
  rect 1.6x1.8 smd: 1(-1.425,0) 2(1.425,0)
  round 0.762 on Mech2: ORIGIN(0,0)
  silkscreen extent -2.51,-1.17 2.51,1.17, body extent -1.6,-0.8 1.6,0.8, height 1.5
POWER_JACK_PTH [mil] "POWER_JACK_PTH"
  round 170 hole 118: GND(0,304) GNDBREAK(186,422) PWR(0,540)
  silkscreen extent -177,119 178,540
SAMTEC_SEAM-30-02.0-L-08-1-A-K-TR [mm]
  round 0.64 smd paste+0.125: A1(18.415,4.445) A2(17.145,4.445) A3(15.875,4.445) A4(14.605,4.445) A5(13.335,4.445) A6(12.065,4.445) A7(10.795,4.445) A8(9.525,4.445) A9(8.255,4.445) A10(6.985,4.445) A11(5.715,4.445) A12(4.445,4.445) A13(3.175,4.445) A14(1.905,4.445) A15(0.635,4.445) A16(-0.635,4.445) A17(-1.905,4.445) A18(-3.175,4.445) A19(-4.445,4.445) A20(-5.715,4.445) A21(-6.985,4.445) A22(-8.255,4.445) A23(-9.525,4.445) A24(-10.795,4.445) A25(-12.065,4.445) A26(-13.335,4.445) A27(-14.605,4.445) A28(-15.875,4.445) A29(-17.145,4.445) A30(-18.415,4.445) B1(18.415,3.175) B2(17.145,3.175) B3(15.875,3.175) B4(14.605,3.175) B5(13.335,3.175) B6(12.065,3.175) B7(10.795,3.175) B8(9.525,3.175) B9(8.255,3.175) B10(6.985,3.175) B11(5.715,3.175) B12(4.445,3.175) B13(3.175,3.175) B14(1.905,3.175) B15(0.635,3.175) B16(-0.635,3.175) B17(-1.905,3.175) B18(-3.175,3.175) B19(-4.445,3.175) B20(-5.715,3.175) B21(-6.985,3.175) B22(-8.255,3.175) B23(-9.525,3.175) B24(-10.795,3.175) B25(-12.065,3.175) B26(-13.335,3.175) B27(-14.605,3.175) B28(-15.875,3.175) B29(-17.145,3.175) B30(-18.415,3.175) C1(18.415,1.905) C2(17.145,1.905) C3(15.875,1.905) C4(14.605,1.905) C5(13.335,1.905) C6(12.065,1.905) C7(10.795,1.905) C8(9.525,1.905) C9(8.255,1.905) C10(6.985,1.905) C11(5.715,1.905) C12(4.445,1.905) C13(3.175,1.905) C14(1.905,1.905) C15(0.635,1.905) C16(-0.635,1.905) C17(-1.905,1.905) C18(-3.175,1.905) C19(-4.445,1.905) C20(-5.715,1.905) C21(-6.985,1.905) C22(-8.255,1.905) C23(-9.525,1.905) C24(-10.795,1.905) C25(-12.065,1.905) C26(-13.335,1.905) C27(-14.605,1.905) C28(-15.875,1.905) C29(-17.145,1.905) C30(-18.415,1.905) D1(18.415,0.635) D2(17.145,0.635) D3(15.875,0.635) D4(14.605,0.635) D5(13.335,0.635) D6(12.065,0.635) D7(10.795,0.635) D8(9.525,0.635) D9(8.255,0.635) D10(6.985,0.635) D11(5.715,0.635) D12(4.445,0.635) D13(3.175,0.635) D14(1.905,0.635) D15(0.635,0.635) D16(-0.635,0.635) D17(-1.905,0.635) D18(-3.175,0.635) D19(-4.445,0.635) D20(-5.715,0.635) D21(-6.985,0.635) D22(-8.255,0.635) D23(-9.525,0.635) D24(-10.795,0.635) D25(-12.065,0.635) D26(-13.335,0.635) D27(-14.605,0.635) D28(-15.875,0.635) D29(-17.145,0.635) D30(-18.415,0.635) E1(18.415,-0.635) E2(17.145,-0.635) E3(15.875,-0.635) E4(14.605,-0.635) E5(13.335,-0.635) E6(12.065,-0.635) E7(10.795,-0.635) E8(9.525,-0.635) E9(8.255,-0.635) E10(6.985,-0.635) E11(5.715,-0.635) E12(4.445,-0.635) E13(3.175,-0.635) E14(1.905,-0.635) E15(0.635,-0.635) E16(-0.635,-0.635) E17(-1.905,-0.635) E18(-3.175,-0.635) E19(-4.445,-0.635) E20(-5.715,-0.635) E21(-6.985,-0.635) E22(-8.255,-0.635) E23(-9.525,-0.635) E24(-10.795,-0.635) E25(-12.065,-0.635) E26(-13.335,-0.635) E27(-14.605,-0.635) E28(-15.875,-0.635) E29(-17.145,-0.635) E30(-18.415,-0.635) F1(18.415,-1.905) F2(17.145,-1.905) F3(15.875,-1.905) F4(14.605,-1.905) F5(13.335,-1.905) F6(12.065,-1.905) F7(10.795,-1.905) F8(9.525,-1.905) F9(8.255,-1.905) F10(6.985,-1.905) F11(5.715,-1.905) F12(4.445,-1.905) F13(3.175,-1.905) F14(1.905,-1.905) F15(0.635,-1.905) F16(-0.635,-1.905) F17(-1.905,-1.905) F18(-3.175,-1.905) F19(-4.445,-1.905) F20(-5.715,-1.905) F21(-6.985,-1.905) F22(-8.255,-1.905) F23(-9.525,-1.905) F24(-10.795,-1.905) F25(-12.065,-1.905) F26(-13.335,-1.905) F27(-14.605,-1.905) F28(-15.875,-1.905) F29(-17.145,-1.905) F30(-18.415,-1.905) G1(18.415,-3.175) G2(17.145,-3.175) G3(15.875,-3.175) G4(14.605,-3.175) G5(13.335,-3.175) G6(12.065,-3.175) G7(10.795,-3.175) G8(9.525,-3.175) G9(8.255,-3.175) G10(6.985,-3.175) G11(5.715,-3.175) G12(4.445,-3.175) G13(3.175,-3.175) G14(1.905,-3.175) G15(0.635,-3.175) G16(-0.635,-3.175) G17(-1.905,-3.175) G18(-3.175,-3.175) G19(-4.445,-3.175) G20(-5.715,-3.175) G21(-6.985,-3.175) G22(-8.255,-3.175) G23(-9.525,-3.175) G24(-10.795,-3.175) G25(-12.065,-3.175) G26(-13.335,-3.175) G27(-14.605,-3.175) G28(-15.875,-3.175) G29(-17.145,-3.175) G30(-18.415,-3.175) H1(18.415,-4.445) H2(17.145,-4.445) H3(15.875,-4.445) H4(14.605,-4.445) H5(13.335,-4.445) H6(12.065,-4.445) H7(10.795,-4.445) H8(9.525,-4.445) H9(8.255,-4.445) H10(6.985,-4.445) H11(5.715,-4.445) H12(4.445,-4.445) H13(3.175,-4.445) H14(1.905,-4.445) H15(0.635,-4.445) H16(-0.635,-4.445) H17(-1.905,-4.445) H18(-3.175,-4.445) H19(-4.445,-4.445) H20(-5.715,-4.445) H21(-6.985,-4.445) H22(-8.255,-4.445) H23(-9.525,-4.445) H24(-10.795,-4.445) H25(-12.065,-4.445) H26(-13.335,-4.445) H27(-14.605,-4.445) H28(-15.875,-4.445) H29(-17.145,-4.445) H30(-18.415,-4.445)
  round 1.27 hole 1.27 unplated: ""(-20.84,-3.05) ""(20.84,0)
  Keep-Out Layer circle w0.127: c-20.84,-3.05 r0.889
  Keep-Out Layer circle w0.127: c20.84,0 r0.889
  silkscreen extent -21.54,-6.07 22.43,7.37
SOT23-5 [mm] "SOT23-5"
  rect 1.1x0.6 smd: 1(-1.3,0.95) 2(-1.3,0) 3(-1.3,-0.95) 4(1.3,-0.95) 5(1.3,0.95)
  round 0.635 on Top Overlay: ""(-1.397,1.905)
  silkscreen extent -0.81,-1.52 0.81,1.52
SW-SMD_4P_6X6 [mm]
  rect 2.1x1.4 smd: 1(-4.55,2.25) 2(4.55,2.25) 3(-4.55,-2.25) 4(4.55,-2.25)
  silkscreen extent -3,-3 3,3, body extent -5,-3 5,3, height 5.13
"TEST POINT" [mil] "TH"
  round 60 hole 40: 1(0,0)
  silkscreen extent -40,-40 40,40

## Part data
+5V GND1 GND2 GND3 GND4 INT1# INT2# PS_POR_B VCC VCC_3V3 VCC_EXT VCCIO VCCIO_1V8 VCCIO_EXT: library part "TEST POINT 1", "CONN HEADER VERT 1POS", Part Number=TSW-101-07-G-S
C3 C6 C7 C8 C9 C10 C11 C12 C13 C14 C17 C18 C19 C20 C21 C22 C23 C24 C25 C26: library part CAP, "CAP CER 0.1UF 16V X7R 0402", Part Number=CL05B104KO5NNNC
C4 C15: library part CAP, "CAP CER 10000PF 16V X7R 0402", Part Number=CL05B103KO5NNNC
C5 C16: library part CAP, "CAP CER 10UF 10V X5R 0402", Part Number=CL05A106MP5NUNC
C27 C29: library part C-USC0603
C28 C30: library part C-USC0603, "CAP CER 10UF 10V X5R 0603", Part Number=CL10A106MP8NNNC
C31 C32 C35 C36: library part CAP, "CAP CER 1UF 16V X7R 0603", Part Number=CL10B105MO8NNWC
C33 C40 C45 C50 C69 C72 C75: library part CAP, "CAP CER 10UF 10V X5R 0603", Part Number=CL10A106MP8NNNC
C34 C39 C46 C49 C70 C73 C76: library part CAP, "CAP CER 0.1UF 16V X7R 0603", Part Number=CL10B104KO8NNNC
C37 C38 C47 C48 C71 C74 C77: library part CAP, "CAP CER  0.01UF 16V X7R 0603", Part Number=CL10B103KO8WPNC
C78 C79 C80 C81 C82 C83 C85 C86 C87 C88 C89 C90 C91 C92 C93 C94 C95 C96: library part CAP, "CAP CER 5PF 16V C0G/NP0 01005", Part Number=CL05C050DB5NNNC
J1 J2: "CONN PWR JACK 2X5.5MM SOLDER", Part Number=PJ-102A
J3: "CONN HD ARRAY PLUG 240P SMD GOLD"
J6 J7: library part HDR-7, "CONN HEADER VERT 7POS 2.54MM", Part Number=TSW-107-07-G-S
J15: "CONN HEADER VERT 2POS 2.54MM", Part Number=TSW-102-07-G-S
JP3 JP4 JP5 JP6 JP10 JP11: "CONN HEADER VERT 3POS 2.54MM", Part Number=TSW-103-07-G-S
JP7: library part X5511FV-10-C70D30-1000_0, "CONN HEADER VERT 2POS 2.54MM", Part Number=TSW-102-07-G-S
JP8: "CONN HEADER VERT 4POS 2.54MM", Part Number=TSW-104-07-G-S
JP9: library part "SW PUSH-S_2", "SWITCH TACTILE SPST-NO 0.05A 12V", Part Number=TL3301AF160QG
L1 L2: library part INDUCTOR, "Ferrite Beads 43 SM BEAD Z=47 OHM @ 100MHz"
LED1 LED2: library part LED, "LED RED CLEAR CHIP SMD", Part Number=LTST-C190EKT
R1 R4 R6 R7: library part RES
R2 R3 R5: library part RES, "RES 0 OHM JUMPER 1/10W 0603", Part Number=RC0603JR-070RL
R10 R11 R12 R13 R14 R15 R17 R24 R25 R26 R27 R28 R29 R30 R31 R32 R33 R34 R35: library part R-US_R0603, "RES 39 OHM 1% 1/16W 0402", Part Number=RC0402FR-0739RL
R20: library part R, "RES SMD 665 OHM 1% 1/10W 0603", Part Number=RC0603FR-07665RL
R21: library part R, "RES SMD 261 OHM 1% 1/10W 0603", Part Number=RC0603FR-07261RL
R22: library part R, "RES 4.7K OHM 1% 1/10W 0603", Part Number=RC0603FR-074K7L
U1: library part TLV757P, "IC REG LINEAR 3.3V 1A SOT23-5"
U3: library part TLV757P, "IC REG LINEAR 1.8V 1A SOT23-5"

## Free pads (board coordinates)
  round 200 hole 125: ""(-2850.51,149.95) ""(-2610.57,2134.86) ""(-390.57,2134.86) ""(-149.53,149.94)
  round 60 on Mech9: ""(-2400.02,653.42)

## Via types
v1: diameter 22, hole 12, Top Layer to Bottom Layer, tented both sides, 368 vias
v2: diameter 20, hole 12, Top Layer to Bottom Layer, tented both sides, 72 vias

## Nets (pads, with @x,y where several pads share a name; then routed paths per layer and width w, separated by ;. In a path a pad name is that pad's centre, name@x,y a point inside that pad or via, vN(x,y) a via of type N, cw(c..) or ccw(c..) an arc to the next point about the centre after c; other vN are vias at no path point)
+5V: +5V.1 C31.1 C33.1 C34.1 C35.1 C37.1 C45.1 C46.1 C47.1 C75.1 C76.1 C77.1 J3.F1 J3.F2 JP5.1 JP6.1 U1.1 U3.1 | length 361.5
  Top Layer w30: C75.1@-2320.02,2000.86 C76.1@-2320.02,2075.86 ; v1(-2274.61,2075.86) C76.1@-2320.02,2075.86 ; v1(-2250.75,2160.66) C77.1@-2320.02,2150.86 C76.1@-2320.02,2075.86
  Bottom Layer w25: v1@-2250.71,2160.62 -2225.25,2160.62 -2225.21,2160.59 -2225.16,2160.59 v1(-2200.29,2135.71) -2200.25,2135.68 J3.F2@-2175.25,2160.68
  other v1: -695.51,1084.95 -635.51,1084.95 -725.51,1119.95 -665.51,1119.95 -605.51,1119.95 -695.51,1494.95 -630.51,1494.95 -725.51,1529.95 -665.51,1529.95 -600.51,1529.95 -565.51,1574.95
CLK1: J3.F8 J7.1 R10.1 | length 2876.8
  Top Layer w5: v1(-1474.5,1953.94) -1426.62,2001.82 -204.96,2001.82 J7.1@-86.44,1883.3
  INT1 w5: v1(-1850.6,2135.97) -1850.6,2189.86 -1730.51,2309.95 -1625.51,2309.95 -1610.51,2294.95 -1610.51,2219.95 -1595.51,2204.95 -1550.51,2204.95 -1535.51,2219.95 -1535.51,2294.95 -1520.51,2309.95 -1415.51,2309.95 -1395.51,2289.95 -1395.51,2134.95 -1370.51,2109.95 -1310.51,2109.95 -1290.51,2109.95 -1275.51,2094.95 -1275.51,2019.95 -1295.51,1999.95 -1453.64,1999.95 -1474.5,1979.1 v1(-1474.5,1953.94)
  Bottom Layer w15: R10.1@-1474.5,1918.54 v1(-1474.5,1953.94)
  Bottom Layer w25: J3.F8@-1875.25,2160.62 v1(-1850.6,2135.97) v1@-1850.57,2135.94
CLK1_1: C78.2 DUT1.K7 R10.2 | length 1441.1
  Top Layer w15: DUT1.K7@-1539.87,1073.1 v2(-1524.51,1088.46) ; v1(-1474.75,1846.89) C78.2@-1474.75,1882.29
  Bottom Layer w5: v2(-1524.51,1088.46) -1535.51,1099.46 -1571,1134.95 -1593.51,1134.95 -1614.51,1155.95 -1614.51,1205.95 -1608.4,1212.07 -1608.4,1304.83 -1637.51,1333.95 -1691.51,1333.95 -1710.51,1352.95 -1710.51,1564.7 -1695.27,1579.95 -1669.51,1579.95 -1655.3,1565.74 -1655.3,1429.74 -1640.51,1414.95 -1605.51,1414.95 -1590.51,1429.95 -1590.51,1644.95 -1474.75,1760.72 v1(-1474.75,1846.89)
  Bottom Layer w15: v1(-1474.75,1846.89) R10.2@-1474.75,1882.29
CLK2: J3.E1 J6.1 R11.1 | length 2876.9
  Top Layer w5: v1(-1925.02,1954.26) -1900.51,1929.76 -1900.51,1812.45 -1743.01,1654.95 -945.51,1654.95 -783.05,1817.42 -380.48,1817.42 -338.01,1774.95 -338.01,1731.29 -306.68,1699.95 -140.51,1699.95 J6.1@-85.51,1754.95
  INT1 w5: v1(-2250.75,2210.66) -2290.51,2170.89 -2290.51,2134.95 -2250.51,2094.95 -2250.51,1994.95 -2175.51,1919.95 -1959.32,1919.95 v1(-1925.02,1954.26)
  Bottom Layer w15: R11.1@-1925.02,1918.86 v1(-1925.02,1954.26)
  Bottom Layer w25: v1@-2250.71,2210.62 -2225.25,2210.62 J3.E1@-2225.21,2210.59
CLK2_1: C79.2 DUT1.K6 R11.2 | length 1480.2
  Top Layer w15: v1(-1925.02,1847.46) C79.2@-1925.02,1882.86 ; v2(-1594.61,1088.46) DUT1.K6@-1579.24,1073.1
  INT1 w5: v1@-1925.27,1847.46 -1925.27,1805.2 -1945.51,1784.95 -2095.51,1784.95 -2125.51,1754.95 -2125.51,1644.95 -2100.51,1619.95 -1997.53,1619.95 -1975.51,1597.93 -1975.51,1199.34 -1881.13,1104.95 -1680.51,1104.95 -1640.51,1064.95 -1618.12,1064.95 v2(-1594.61,1088.46)
  Bottom Layer w15: v1(-1925.02,1847.46) R11.2@-1925.02,1882.86
CS1#: J3.D6 J7.3 R14.1 | length 2853.9
  Top Layer w5: v1(-1950.29,2285.61) -1975.51,2310.83 -1975.51,2439.95 -1930.51,2484.95 -1475.51,2484.95 -1435.51,2444.95 -1435.51,2329.95 -1400.51,2294.95 -1350.51,2294.95 -1320.51,2264.95 -1320.51,2205.83 -1346.39,2179.95 -1470.51,2179.95 -1524.93,2125.53 v1(-1524.93,1954.25)
  INT1 w5: v1(-1524.93,1954.25) -1505.63,1934.95 -1245.51,1934.95 -1185.51,1994.95 -396.24,1994.95 J7.3@-285.51,1884.22
  Bottom Layer w15: R14.1@-1524.93,1918.85 v1(-1524.93,1954.25)
  Bottom Layer w25: J3.D6@-1975.25,2260.57 v1@-1950.25,2285.57
CS1#_1: C82.2 DUT1.L7 R14.2 | length 1441.4
  Top Layer w15: v2(-1555.24,1018.37) DUT1.L7@-1539.87,1033.73 ; v1@-1524.93,1847.14 C82.2@-1524.93,1882.54
  Bottom Layer w5: v2(-1555.24,1018.37) -1540.51,1033.09 -1540.51,1074.95 -1573.21,1107.65 -1645.51,1107.65 -1653.21,1099.95 -1735.51,1099.95 -1835.51,1199.95 -1835.51,1276.29 -1816.85,1294.95 -1775.51,1294.95 -1760.51,1309.95 -1760.51,1339.95 -1775.61,1355.04 -1805.61,1355.04 -1824.92,1374.36 -1824.92,1473.15 -1756.5,1541.57 -1756.5,1649.97 -1740.51,1665.95 -1634.51,1665.95 -1525.18,1775.28 v1(-1525.18,1847.2)
  Bottom Layer w15: v1(-1525.18,1847.2) R14.2@-1525.18,1882.6
CS2#: J3.F6 J6.3 R15.1 | length 2877
  Top Layer w5: v1(-1424.5,1953.94) -1410.49,1967.95 -872.51,1967.95 -397.51,1967.95 -340.43,1910.87 -340.43,1809.87 J6.3@-285.51,1754.95
  INT1 w5: v1(-1950.33,2185.62) -1776,2359.95 -1250.51,2359.95 -1225.51,2334.95 -1225.51,2266.95 -1242.51,2249.95 -1309.51,2249.95 -1325.51,2233.95 -1325.51,2185.95 -1309.51,2169.95 -1243.51,2169.95 -1225.51,2151.95 -1225.51,2011.95 -1257.51,1979.95 -1398.49,1979.95 v1(-1424.5,1953.94)
  Bottom Layer w15: R15.1@-1424.5,1918.54 v1(-1424.5,1953.94)
  Bottom Layer w25: J3.F6@-1975.29,2160.66 v1(-1950.33,2185.62)
CS2#_1: C83.2 DUT1.J8 R15.2 | length 1441
  Top Layer w15: v2(-1515.87,1127.83) DUT1.J8@-1500.5,1112.47 ; v1@-1424.5,1847.46 C83.2@-1424.5,1882.86
  Bottom Layer w5: v2(-1515.87,1127.83) -1515.87,1198.91 -1518.99,1202.03 -1518.99,1263.42 -1591.23,1335.67 -1591.23,1374.23 -1580.51,1384.95 -1544.35,1384.95 -1532.02,1397.29 -1532.02,1658.45 -1520.51,1669.95 -1485.51,1669.95 -1475.51,1659.95 -1475.51,1444.95 -1465.51,1434.95 -1435.51,1434.95 -1424.75,1445.72 v1(-1424.75,1846.89)
  Bottom Layer w15: v1(-1424.75,1846.89) R15.2@-1424.75,1882.29
DC_I2C_SCL: J3.D23 | length 35.4
  Bottom Layer w25: v1@-1150.25,2235.68 J3.D23@-1125.25,2260.68
  other v1: -1150.29,2235.71
DC_I2C_SDA: J3.D24 | length 35.4
  Bottom Layer w25: v1@-1100.25,2235.68 J3.D24@-1075.25,2260.68
  other v1: -1100.29,2235.71
DC_PRSNT: J3.D25 R2.1 | length 86.6
  Top Layer w30: v1(-1050.29,2235.61) -1049.69,2236.21 R2.1@-1049.69,2286.58
  Bottom Layer w25: v1@-1050.25,2235.57 J3.D25@-1025.25,2260.57
GND: C31.2 C32.2 C33.2 C34.2 C35.2 C36.2 C37.2 C38.2 C39.2 C40.2 C45.2 C46.2 C47.2 C48.2 C49.2 C50.2 C69.2 C70.2 C71.2 C72.2 C73.2 C74.2 C75.2 C76.2 C77.2 C78.1 C79.1 C80.1 C81.1 C82.1 C83.1 C85.1 C86.1 C87.1 C88.1 C89.1 C90.1 C91.1 C92.1 C93.1 C94.1 C95.1 C96.1 GND1.1 GND2.1 GND3.1 GND4.1 J3.A3 J3.A4 J3.A7 J3.A8 J3.A11 J3.A12 J3.A15 J3.A16 J3.A19 J3.A20 J3.A23 J3.A24 J3.A27 J3.A28 J3.B1 J3.B2 J3.B5 J3.B6 J3.B9 J3.B10 J3.B13 J3.B14 J3.B17 J3.B18 J3.B21 J3.B22 J3.B25 J3.B26 J3.C3 J3.C6 J3.C9 J3.C12 J3.C15 J3.C18 J3.C21 J3.C24 J3.C27 J3.C28 J3.D3 J3.D4 J3.D7 J3.D10 J3.D13 J3.D16 J3.D19 J3.D22 J3.D29 J3.E3 J3.E6 J3.E9 J3.E12 J3.E15 J3.E18 J3.E21 J3.E24 J3.E27 J3.E28 J3.F3 J3.F4 J3.F7 J3.F10 J3.F13 J3.F16 J3.F19 J3.F22 J3.G2 J3.G5 J3.G8 J3.G11 J3.G14 J3.G17 J3.G20 J3.G23 J3.G28 J3.H3 J3.H4 J3.H7 J3.H10 J3.H13 J3.H16 J3.H19 J3.H22 J3.H27 J6.2 J7.2 JP3.3 JP4.3 JP9.3 JP9.4 JP10.3 JP11.3 L1.1 L2.1 LED1.2 LED2.2 R2.2 U1.2 U3.2 | length 5465
  Top Layer w20: v1@-2750.51,2325.55 LED1.2@-2750.51,2360.95 ; C34.2@-700.51,1229.95 v1(-700.51,1264.95) ; C46.2@-700.51,1639.95 v1(-700.51,1674.95) ; C37.2@-625.51,1229.95 v1(-625.51,1264.95) ; C47.2@-625.51,1639.95 v1(-625.51,1674.95) ; -622.51,399.55 C96.1@-622.51,434.95 ; v1(-597.09,1039.95) U1.2@-561.69,1039.95 ; v1@-597.09,1449.95 U3.2@-561.69,1449.95 ; C49.2@-490.51,1639.95 v1(-490.51,1674.95) ; C39.2@-455.51,1229.95 v1(-455.51,1264.95) ; C48.2@-415.51,1639.95 v1(-415.51,1674.95) ; C38.2@-380.51,1229.95 v1(-380.51,1264.95) ; v1@-280.51,2325.55 LED2.2@-280.51,2360.95
  Top Layer w30: v1(-1150.25,2285.57) -1149.24,2286.58 R2.2@-1109.69,2286.58
  Bottom Layer w20: v1(-2150.91,2030.63) J3.H3@-2125.29,2060.66
  Bottom Layer w25: v1(-2250.25,2385.62) J3.B1@-2225.25,2360.62 ; J3.B1@-2225.21,2360.61 v1(-2200.25,2385.57) v1@-2150.29,2335.61 ; v1(-2200.25,2085.68) -2150.29,2135.64 -2125.25,2160.68 v1@-2150.21,2185.64 ; v1(-2150.25,2185.68) J3.E3@-2125.25,2210.68 ; v1(-2150.25,2335.57) J3.C3@-2125.25,2310.57 ; J3.D3@-2125.25,2260.57 v1(-2150.25,2235.57) J3.E3@-2125.29,2210.66 ; v1(-2125.25,2436.08) J3.A3@-2125.25,2410.62 ; J3.A3@-2125.21,2410.59 J3.A4@-2075.29,2410.59 ; J3.D3@-2125.16,2260.59 v1(-2100.2,2235.62) J3.D4@-2075.2,2260.62 ; v1@-2100.33,2235.62 J3.E3@-2125.29,2210.66 ; J3.F4@-2075.25,2160.68 J3.G5@-2025.29,2110.66 ; v1(-2075.25,2436.08) -2075.25,2410.68 v1(-2050.29,2385.66) ; J3.H4@-2075.21,2060.66 -2047.88,2033.32 v1(-2047.29,2033.32) ; J3.H4@-2075.21,2060.71 J3.G5@-2025.25,2110.68 ; v1(-2050.29,2385.66) J3.B5@-2025.29,2360.66 v1@-2000.33,2385.62 ; v1(-2000.25,2385.57) J3.B6@-1975.25,2360.57 ; J3.E6@-1975.29,2210.66 J3.D7@-1925.36,2260.62 ; J3.C6@-1975.25,2310.62 v1(-1950.25,2335.62) ; J3.B6@-1975.29,2360.66 v1@-1950.33,2335.7 ; J3.D7@-1925.31,2260.62 v1(-1900.31,2285.62) ; v1(-1925.29,2025.31) J3.H7@-1925.29,2060.66 ; J3.F7@-1925.25,2160.57 v1(-1900.29,2135.61) J3.G8@-1875.31,2110.62 ; v1(-1925.25,2436.08) J3.A7@-1925.25,2410.7 ; J3.H7@-1925.21,2060.66 v1@-1900.25,2085.62 ; v1(-1900.25,2085.68) J3.G8@-1875.31,2110.62 ; J3.A8@-1875.29,2410.66 J3.A7@-1925.25,2410.7 ; J3.G8@-1875.25,2110.68 J3.G8@-1875.31,2110.62 ; v1(-1875.25,2436.08) -1875.25,2410.62 v1(-1850.25,2385.57) J3.B9@-1825.25,2360.57 ; v1(-1850.25,2235.62) v1@-1800.29,2185.66 ; J3.B9@-1825.29,2360.53 v1(-1850.25,2335.57) v1@-1800.29,2285.61 ; J3.B9@-1825.29,2360.66 v1@-1800.33,2385.62 ; v1(-1800.25,2185.57) v1@-1750.29,2135.61 ; v1(-1800.25,2285.57) J3.D10@-1775.25,2260.57 ; v1(-1800.25,2385.57) J3.B10@-1775.25,2360.57 ; J3.H10@-1775.29,2060.66 -1765.51,2050.88 v1(-1765.51,2019.95) ; v1(-1750.25,2135.57) J3.G11@-1725.25,2110.57 ; v1(-1725.25,2436.08) J3.A11@-1725.25,2410.62 ; v1(-1700.25,2235.57) J3.E12@-1675.25,2210.57 ; v1(-1700.25,2335.57) J3.C12@-1675.25,2310.57 ; v1(-1675.25,2436.08) J3.A12@-1675.25,2410.62 ; J3.E12@-1675.21,2210.53 v1(-1650.25,2185.57) J3.F13@-1625.25,2160.57 ; J3.C12@-1675.21,2310.53 v1(-1650.25,2285.57) J3.D13@-1625.25,2260.57 ; v1(-1650.25,2385.57) -1625.25,2360.57 v1@-1600.29,2385.53 ; v1(-1650.25,2385.57) -1675.21,2410.59 J3.A12@-1675.29,2410.59 ; v1(-1649.85,2084.77) J3.H13@-1624.85,2059.77 ; J3.F13@-1625.21,2160.59 v1(-1600.25,2135.62) J3.G14@-1575.25,2110.62 ; v1(-1600.25,2385.57) -1525.25,2310.57 v1(-1500.25,2335.57) ; v1(-1525.25,2436.08) J3.A15@-1525.25,2410.62 ; J3.D16@-1475.34,2260.59 v1(-1500.31,2235.62) -1525.31,2210.62 J3.F16@-1475.31,2160.62 ; J3.A16@-1475.33,2410.62 J3.A15@-1525.25,2410.62 ; J3.F16@-1475.25,2160.68 v1(-1450.25,2135.68) ; J3.D16@-1475.25,2260.57 v1(-1450.25,2285.57) ; v1(-1475.25,2436.08) J3.A16@-1475.25,2410.62 ; v1(-1475.21,2025.31) J3.H16@-1475.21,2060.66 ; v1@-1450.25,2135.62 J3.G17@-1425.29,2110.66 v1(-1400.25,2085.68) ; J3.B17@-1425.25,2360.57 v1(-1400.25,2385.57) ; J3.B17@-1425.25,2360.62 J3.A16@-1475.25,2410.62 ; v1@-1400.21,2385.53 J3.B18@-1375.25,2360.57 ; J3.C18@-1375.25,2310.57 v1(-1350.25,2335.57) ; -1360.63,2225.24 J3.D19@-1325.31,2260.57 ; v1(-1350.31,2235.62) -1375.28,2210.65 J3.F19@-1325.29,2160.66 v1(-1300.25,2135.68) ; v1@-1350.29,2335.61 J3.B18@-1375.25,2360.57 ; v1(-1350.25,2385.57) J3.B18@-1375.25,2360.57 ; v1@-1350.25,2385.7 J3.A19@-1325.29,2410.66 ; v1(-1325.51,2029.95) -1325.29,2030.18 J3.H19@-1325.29,2060.66 ; J3.D19@-1325.25,2260.57 v1(-1300.25,2285.57) ; v1(-1325.25,2436.08) J3.A19@-1325.25,2410.66 ; J3.H19@-1325.21,2060.66 J3.H19@-1324.48,2059.92 ; v1@-1300.25,2135.62 J3.G20@-1275.29,2110.66 v1(-1250.25,2085.68) ; J3.A20@-1275.29,2410.66 J3.A19@-1325.25,2410.66 ; v1(-1275.25,2436.08) J3.A20@-1275.25,2410.62 ; v1(-1250.25,2385.62) v1@-1200.29,2335.66 ; v1@-1250.29,2385.66 J3.A20@-1275.25,2410.62 ; J3.E21@-1225.31,2210.62 v1(-1200.31,2235.62) ; J3.C21@-1225.25,2310.57 v1(-1200.25,2335.57) ; J3.B21@-1225.21,2360.66 v1(-1200.25,2385.62) -1175.25,2360.62 v1@-1200.21,2335.66 ; v1(-1200.25,2135.68) J3.F22@-1175.25,2160.68 ; v1@-1200.25,2235.7 J3.D22@-1175.29,2260.66 ; v1(-1175.51,2029.95) -1175.29,2030.18 J3.H22@-1175.29,2060.66 ; J3.D22@-1175.25,2260.57 v1(-1150.25,2285.57) ; J3.H22@-1175.21,2060.71 v1(-1150.25,2085.68) J3.G23@-1125.25,2110.68 ; v1(-1125.25,2436.08) -1125.25,2410.66 J3.A24@-1075.29,2410.66 ; v1(-1100.31,2335.62) J3.C24@-1075.31,2310.62 ; J3.E24@-1075.25,2210.68 v1(-1050.25,2185.68) ; v1(-1075.25,2436.08) J3.A24@-1075.25,2410.62 ; J3.B25@-1025.31,2360.62 v1(-1000.31,2385.62) J3.B26@-975.29,2360.66 J3.B26@-975.29,2360.66 ; J3.B26@-975.31,2360.62 v1(-950.31,2385.62) J3.A27@-925.34,2410.59 ; v1(-925.51,2029.95) -925.29,2030.18 J3.H27@-925.29,2060.66 ; J3.E27@-925.31,2210.62 v1(-900.31,2235.62) J3.E28@-875.29,2210.66 ; J3.C27@-925.31,2310.62 v1(-900.31,2335.62) ; v1(-925.25,2436.08) -925.25,2410.66 J3.A28@-875.21,2410.66 ; J3.E28@-875.31,2210.62 v1(-850.31,2235.62) J3.D29@-825.34,2260.59 ; J3.C28@-875.31,2310.62 v1(-850.31,2335.62) ; J3.G28@-875.25,2110.68 v1(-850.25,2085.68) ; J3.A28@-875.25,2410.62 J3.A28@-875.21,2410.66 ; v1(-875.21,2436.12) J3.A28@-875.21,2410.66 ; J3.D29@-825.31,2260.62 v1(-800.31,2285.62) ; J3.A3@-2125.29,2410.59 J3.A3@-2125.25,2410.62 ; J3.A4@-2075.29,2410.59 J3.A4@-2075.25,2410.62 ; J3.A7@-1925.25,2410.62 J3.A7@-1925.25,2410.7 ; J3.A7@-1925.29,2410.59 J3.A7@-1925.25,2410.62 ; J3.A11@-1725.29,2410.59 J3.A11@-1725.25,2410.62 ; J3.A11@-1725.25,2410.62 -1675.33,2410.62 J3.A12@-1675.29,2410.59 ; J3.A12@-1675.29,2410.59 J3.A12@-1675.25,2410.62 ; J3.A15@-1525.29,2410.59 J3.A15@-1525.25,2410.62 ; J3.A16@-1475.29,2410.59 J3.A16@-1475.25,2410.62 ; J3.A20@-1275.29,2410.59 J3.A20@-1275.25,2410.62 ; J3.A24@-1075.29,2410.59 J3.A24@-1075.25,2410.62 ; J3.A19@-1325.29,2410.59 J3.A19@-1325.25,2410.62 ; J3.A23@-1125.29,2410.59 J3.A23@-1125.25,2410.62 ; J3.A27@-925.29,2410.59 J3.A27@-925.25,2410.62
  other v1: -1650.51,149.95 -1500.51,149.95 -1350.51,149.95 -1200.51,149.95 -1050.51,149.95 -900.51,149.95 -2150.51,174.95 -2000.51,174.95 -1800.51,174.95 -2150.5,324.54 -2000.5,324.54 -1800.5,324.54 -1650.5,324.54 -1500.5,324.54 -1350.5,324.54 -1200.5,324.54 -1050.5,324.54 -900.5,324.54 -120.51,369.95 -2300.5,474.54 -2150.5,474.54 -2000.5,474.54 -1850.5,474.54 -1700.5,474.54 -1550.5,474.54 -1400.5,474.54 -1250.5,474.54 -1100.5,474.54 -950.5,474.54 -1550.5,624.54 -1400.5,624.54 -2750.5,674.54 -1100.5,674.54 -2000.5,774.54 -1875.5,774.54 -1400.5,774.54 -1250.5,774.54 -2091.5,805.54 -2775.51,824.95 -1100.5,824.54 -950.5,824.54 -2092.5,874.54 -2000.5,899.54 -1875.5,899.54 -1100.5,974.54 -948.01,997.45 -1880.51,1004.95 -2000.5,1024.54 -2900.51,1049.95 -2150.51,1099.95 -1950.51,1119.95 -1100.5,1124.54 -2000.5,1174.54 -1895.51,1194.95 -2375.51,1237.45 -2313.01,1237.45 -2900.51,1249.95 -2750.51,1249.95 -1100.5,1274.54 -1506.16,1287.42 -660.51,1299.95 -500.51,1309.95 -410.51,1309.95 -1451.81,1311 -1840.2,1322.12 -2150.5,1324.54 -2000.5,1324.54 -1728.5,1325.54 -1950.5,1327.54 -1899.5,1327.54 -1390.3,1352.35 -1534.5,1355.54 -1271.18,1369.98 -1448.5,1375.54 -1667.67,1383.31 -680.51,1409.95 -1950.51,1422.45 -1898.01,1422.45 -1100.5,1424.54 -1332.5,1437.54 -597.34,1450.2 -1623.55,1459.04 -1172.51,1458.95 -1558.68,1460.1 -1502.94,1476.75 -1449.1,1478.22 -1399.5,1479.54 -1844.5,1492.54 -1260.51,1499.95 -1749.5,1504.54 -1325.51,1514.95 -2900.51,1524.95 -1813.01,1524.95 -1160.51,1529.95 -1950.5,1531.54 -1886.5,1533.54 -1450.3,1563.15 -1400.14,1571.18 -2150.5,1574.54 -2000.5,1574.54 -1620.51,1579.95 -1560.51,1579.95 -1330.51,1579.95 -1200.51,1579.95 -1265.44,1586.27 -1506.07,1587.75 -1730.51,1589.95 -2060.51,1674.95 -1820.51,1674.95 -750.51,1699.95 -1880.51,1709.95 -1700.24,1739.12 -2080.51,1739.95 -1640.18,1743.28 -2010.51,1749.95 -1804.23,1756.76 -1450.51,1759.95 -1253.21,1761.31 -2702.24,1770.96 -2900.51,1774.95 -1600.45,1782.55 -1850.6,1815.7 -1800.07,1815.7 -1750.2,1815.7 -1551.09,1815.89 -1499.51,1815.95 -1449.5,1815.95 -1399.5,1815.95 -1346.5,1815.95 -742.48,1858.73 -884.64,1909.28 -742.48,1909.28 -2234.16,1936.72 -2090.51,1969.95 -2160.51,1989.95 -2226.35,2006.46 -2430.5,2011.54 -1549.58,2015.8 -2750.5,2024.54 -1845.51,2024.95 -200.5,2024.54 -50.5,2024.54 -1991.51,2025.31 -1600.29,2035.66 -2430.5,2076.54 -2150.25,2135.68 -2430.5,2145.54 -2900.5,2174.54 -2750.5,2174.54 -200.5,2174.54 -50.5,2174.54 -482.5,2296.54 -2576.09,2312.03 -2900.5,2324.54 -200.5,2324.54 -50.5,2324.54 -2750.76,2325.3 -280.76,2325.3 -482.5,2346.54 -2575.58,2389.51 -625.51,2449.95 -500.51,2449.95 -2578.1,2460.45 -2900.5,2474.54 -200.5,2474.54 -50.5,2474.54
GND1_EXT: C27.2 C28.2 J1.GND J1.GNDBREAK L1.2 | length 768.7
  Bottom Layer w35: C27.2@-2343.65,963.46 -2292.85,963.46 C28.2@-2264.46,991.86
  Bottom Layer w50: J1.GND@-2752.46,1085.86 J1.GNDBREAK@-2634.46,899.86 ; J1.GNDBREAK@-2642.51,899.86 -2584.51,841.86 L1.2@-2334.46,841.86 -2334.46,954.27 C27.2@-2343.65,963.46
GND2_EXT: C29.2 C30.2 J2.GND J2.GNDBREAK L2.2 | length 727.4
  Bottom Layer w35: C29.2@-2352.5,1558.55 -2291.02,1558.55 C30.2@-2263.23,1586.35
  Bottom Layer w50: J2.GND@-2752.46,1609.95 J2.GNDBREAK@-2634.46,1423.95 -2611.01,1447.39 L2.2@-2350.02,1447.39 -2350.02,1556.07 C29.2@-2352.5,1558.55
HBP0: JP3.2 R32.1 | length 92
  Bottom Layer w20: R32.1@-393.33,755.63 JP3.2@-301.33,755.63
HBP0_1: C93.2 DUT1.G10 R32.2 | length 1398.4
  Top Layer w5: DUT1.G10@-1421.76,1191.21 -1421.76,1243.7 -1365.51,1299.95 -1200.51,1299.95 -840.51,939.95 -530.51,939.95 -465.51,874.95 -465.51,756.42 v1(-464.98,755.88)
  Top Layer w15: DUT1.G10@-1421.89,1191.34 DUT1.G10@-1421.76,1191.21
  Top Layer w20: v1@-464.73,755.63 C93.2@-429.33,755.63
  Bottom Layer w20: v1@-464.73,755.63 R32.2@-429.33,755.63
HBP1: JP4.2 R35.1 | length 92
  Bottom Layer w20: R35.1@-622.51,434.95 JP4.2@-530.51,434.95
HBP1_1: C96.2 DUT1.G11 R35.2 | length 1436.6
  Top Layer w15: DUT1.G11@-1382.39,1191.21 v2(-1382.39,1213.42)
  Top Layer w20: v1@-693.91,434.95 C96.2@-658.51,434.95
  INT1 w5: v2(-1382.39,1213.42) -1343.01,1174.04 -1343.01,947.45 -1163.01,767.45 -1163.01,482.45 -1075.51,394.95 -734.41,394.95 v1(-694.16,435.2)
  Bottom Layer w20: v1@-693.91,434.95 R35.2@-658.51,434.95
HBP2: JP10.2 R33.1 | length 95.2
  Bottom Layer w20: R33.1@-625.33,754 -531.47,754 JP10.2@-530.51,754.95
HBP2_1: C94.2 DUT1.H12 R33.2 | length 1436.8
  Top Layer w15: DUT1.H12@-1343.02,1151.84 -1342.92,1151.95 v2(-1317.56,1151.95)
  Top Layer w20: v1(-696.98,754.25) C94.2@-661.58,754.25
  INT1 w5: v2(-1317.56,1151.95) -1272.51,1151.95 -1220.51,1099.95 -1220.51,989.95 -1155.51,924.95 -1030.51,924.95 -995.51,959.95 -995.51,1134.95 -950.51,1179.95 -820.51,1179.95 -773.2,1132.64 -773.2,998.72 -696.98,922.49 v1(-696.98,754.25)
  Bottom Layer w20: v1@-696.73,754 R33.2@-661.33,754
HTBSEL: JP11.2 R34.1 | length 86
  Bottom Layer w20: R34.1@-387.33,435.63 JP11.2@-301.33,435.63
HTBSEL_1: C95.2 DUT1.J12 R34.2 | length 1398.5
  Top Layer w5: DUT1.J12@-1343.02,1112.47 -1153.03,1112.47 -775.51,734.95 -775.51,619.95 -721.42,565.86 -629.61,565.86 -620.51,574.95 -600.51,594.95 -495.51,594.95 -458.98,558.42 v1(-458.98,435.88)
  Top Layer w20: DUT1.J12@-1343.02,1112.47 DUT1.J12@-1342.93,1112.38 ; v1@-458.73,435.63 C95.2@-423.33,435.63
  Bottom Layer w20: v1@-458.73,435.63 R34.2@-423.33,435.63
INT1#: INT1#.1 R12.1 | length 187.3
  Bottom Layer w10: R12.1@-1325.02,1918.86 -1244.42,1918.86 -1225.51,1899.95 INT1#.1@-1145.51,1899.95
